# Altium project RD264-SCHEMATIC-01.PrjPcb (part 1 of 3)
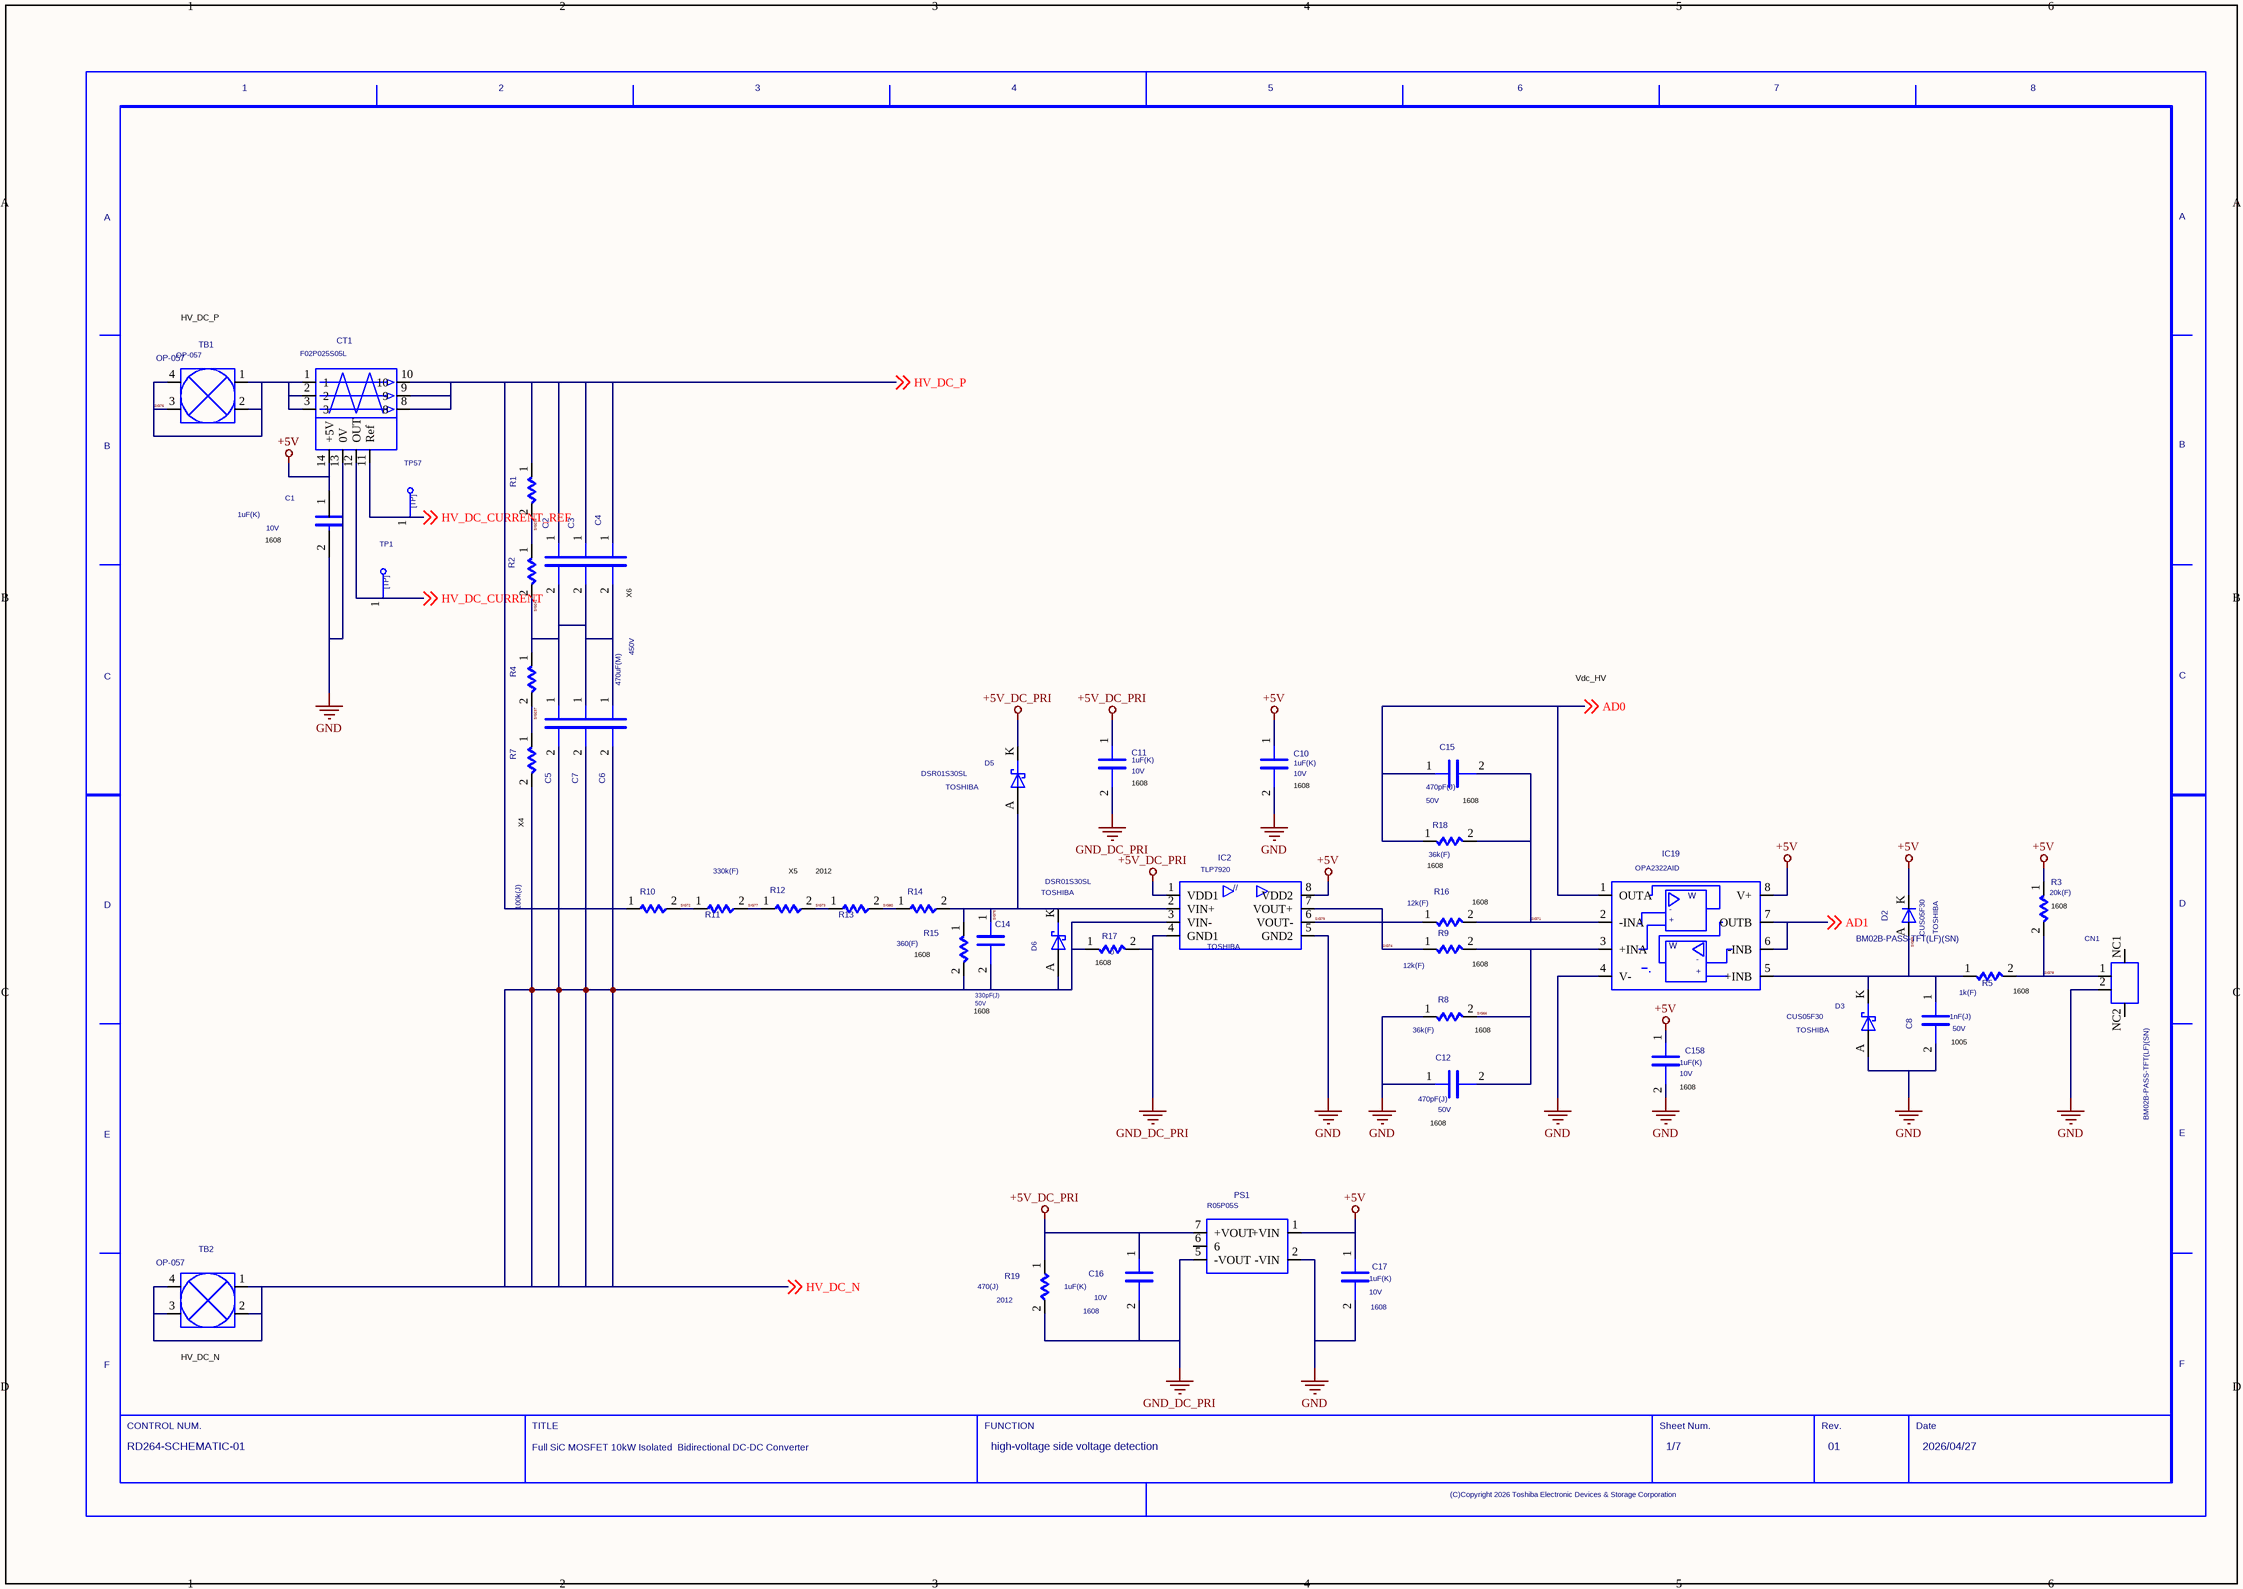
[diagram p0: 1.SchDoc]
7 sheets, 514 parts. Net scope: global (net labels, ports and power ports of the same name join across sheets).
Sheets:
  1.SchDoc
  2.SchDoc
  3.SchDoc
  4.SchDoc
  5.SchDoc
  6.SchDoc
  7.SchDoc

## Sheet 1.SchDoc
size 420 x 297 mm

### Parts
(Parts that share a designator on the sheet are numbered #1, #2 ... from top to bottom, then left to right.)
C1  VAL1: 1uF(K)  VAL2: 10V  (hidden comment: C)
C2  ESMR451VSN471MR40S  (value not drawn)
C3  ESMR451VSN471MR40S  (value not drawn)
C4  VAL1: 470uF(M)  VAL2: 450V  (hidden comment: ESMR451VSN471MR40S)
C5  ESMR451VSN471MR40S  (value not drawn)
C6  ESMR451VSN471MR40S  (value not drawn)
C7  ESMR451VSN471MR40S  (value not drawn)
C8  VAL1: 1nF(J)  VAL2: 50V  (hidden comment: GRM1555C1H102JA01D)
C10  VAL1: 1uF(K)  VAL2: 10V  (hidden comment: GRM188R71A105KA61D)
C11  VAL1: 1uF(K)  VAL2: 10V  (hidden comment: GRM188R71A105KA61D)
C12  VAL1: 470pF(J)  VAL2: 50V  (hidden comment: GRM1885C1H471JA01D)
C14  VAL1: 330pF(J)  VAL2: 50V  (hidden comment: GRM1885C1H331JA01D)
C15  VAL1: 470pF(J)  VAL2: 50V  (hidden comment: GRM1885C1H471JA01D)
C16  VAL1: 1uF(K)  VAL2: 10V  SIZECODESMD: 1608  (hidden comment: GRM188R71A105KA61D)
C17  VAL1: 1uF(K)  VAL2: 10V  SIZECODESMD: 1608  (hidden comment: GRM188R71A105KA61D)
C158  VAL1: 1uF(K)  VAL2: 10V  (hidden comment: GRM188R71A105KA61D)
CN1  BM02B-PASS-TFT(LF)(SN)
CT1  F02P025S05L
D2  USERCOMPTEXT3: TOSHIBA  (hidden comment: CUS05F30)
D3  VAL3: CUS05F30  USERCOMPTEXT3: TOSHIBA  (hidden comment: SBD)
D5  VAL3: DSR01S30SL  USERCOMPTEXT3: TOSHIBA  (hidden comment: SBD)
D6  VAL3: DSR01S30SL  USERCOMPTEXT3: TOSHIBA  (hidden comment: SBD)
IC2  VAL3: TLP7920  USERCOMPTEXT3: TOSHIBA  (hidden comment: TLP7920(LF5,TP5))
IC19  VAL3: OPA2322AID  (hidden comment: OPA2322AIDGKR)
PS1  R05P05S
R1  ROX5SJ100K  (value not drawn)
R2  ROX5SJ100K  (value not drawn)
R3  VAL1: 20k(F)  (hidden comment: RK73H1JTTD2002F)
R4  ROX5SJ100K  (value not drawn)
R5  VAL1: 1k(F)  (hidden comment: RK73H1JTTD1001F)
R7  VAL1: 100k(J)  (hidden comment: ROX5SJ100K)
R8  VAL1: 36k(F)  (hidden comment: RK73G1JTTD3602F)
R9  VAL1: 12k(F)  (hidden comment: RK73G1JTTD1202F)
R10  RK73H2ATTD3303F  (value not drawn)
R11  RK73H2ATTD3303F  (value not drawn)
R12  VAL1: 330k(F)  (hidden comment: RK73H2ATTD3303F)
R13  RK73H2ATTD3303F  (value not drawn)
R14  RK73H2ATTD3303F  (value not drawn)
R15  VAL1: 360(F)  (hidden comment: RK73G1JTTD3600F)
R16  VAL1: 12k(F)  (hidden comment: RK73G1JTTD1202F)
R17  VAL1: 0  (hidden comment: RK73Z1JTTD)
R18  VAL1: 36k(F)  (hidden comment: RK73G1JTTD3602F)
R19  VAL1: 470(J)  SIZECODESMD: 2012  (hidden comment: RK73B2ATTD471J)
TB1  OP-057
TB2  OP-057
TP1  TP  (value not drawn)
TP57  TP  (value not drawn)
U?#1  DATE: 2026/04/27  DRAWINGNUMBER: RD264-SCHEMATIC-01  TITLE: Full SiC MOSFET 10kW Isolated / Bidirectional DC-DC Converter  FUNCTION: high-voltage side voltage detection  SHEETNUMBER: 1/7  REVISION: 01  (hidden comment: WAKU_DEF100)

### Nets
+5V: C1.1 C10.1 C17.1 C158.1 CT1.14(+5V) D2.K(C) IC2.8(VDD2) IC19.8(V+) PS1.1(+VIN) R3.1
+5V_DC_PRI: C11.1 C16.1 D5.K(C) IC2.1(VDD1) PS1.7(+VOUT) R19.1
GND: C1.2 C8.2 C10.2 C12.1 C17.2 C158.2 CN1.2 CT1.13(0V) D3.A IC2.5(GND2) IC19.4(V-) PS1.2(-VIN) R8.1
GND_DC_PRI: C11.2 C16.2 IC2.4(GND1) PS1.5(-VOUT) R17.2 R19.2
AD0: C15.1 IC19.1(OUTA) R18.1 ; off-sheet AD0
AD1: IC19.6(-INB) IC19.7(OUTB) ; off-sheet AD1
HV_DC_CURRENT: CT1.12(OUT) TP1.1 ; off-sheet HV_DC_CURRENT
HV_DC_CURRENT_REF: CT1.11(Ref) TP57.1 ; off-sheet HV_DC_CURRENT_REF
HV_DC_N: C5.2 C6.2 C7.2 C14.2 D6.A IC2.3(VIN-) R7.2 R15.2 R17.1 TB2.1 TB2.2 TB2.3 TB2.4 ; off-sheet HV_DC_N
HV_DC_P: C2.1 C3.1 C4.1 CT1.8 CT1.9 CT1.10 R1.1 R10.1 ; off-sheet HV_DC_P
SIG66: C12.2 IC19.3(+INA) R8.2 R9.2
SIG69: C8.1 D2.A D3.K(C) IC19.5(+INB) R5.1
SIG71: C15.2 IC19.2(-INA) R16.2 R18.2
SIG72: R10.2 R11.1
SIG73: R12.2 R13.1
SIG74: IC2.7(VOUT+) R9.1
SIG75: C14.1 D5.A D6.K(C) IC2.2(VIN+) R14.2 R15.1
SIG76: CT1.1 CT1.2 CT1.3 TB1.1 TB1.2 TB1.3 TB1.4
SIG77: R11.2 R12.1
SIG78: CN1.1 R3.2 R5.2
SIG79: IC2.6(VOUT-) R16.1
SIG80: R13.2 R14.1
SIG237: R4.2 R7.1
SIG238: R1.2 R2.1
SIG241: C2.2 C3.2 C4.2 C5.1 C6.1 C7.1 R2.2 R4.1

Not connected (* = marked no-connect by the designer): CN1 NC1(P1) NC2(P2); PS1 6

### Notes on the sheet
- HV_DC_P
- (near C1) 1608
- (near C4) X6
- Vdc_HV
- (near C11) 1608
- (near C10) 1608
- 1608
- (near R7) X4
- (near R18) 1608
- (near R12) X5
- 2012
- (near R16) 1608
- (near R3) 1608
- (near R17) 1608
- (near R9) 1608
- (near R5) 1608
- (near R8) 1608
- (near C8) 1005
- (near C12) 1608
- (near C158) 1608
- (near TB2) HV_DC_N

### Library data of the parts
C1 = C: OriginalSymbolOrigin: (2540,7620); COMP: C-GRM188R71A105KA61D
C2 = C_Dup1: ORIGINALSYMBOLORIGIN: (0,4826); COMP: C-ESMR451VSN471MR40S; TIME: 14:31:23; UPDATEUSER: t5459927; SAVECOUNT: 1; INSTANCENAME: INS17096676; REFERENCE TEMPLATE: C; COMPONENTNAME: C_C.Normal_package; NOTE: 470uF 450V; VAL1: 470uF(M); VAL2: 450V
C3 = C_Dup1: ORIGINALSYMBOLORIGIN: (0,4826); COMP: C-ESMR451VSN471MR40S; TIME: 14:31:23; UPDATEUSER: t5459927; SAVECOUNT: 1; INSTANCENAME: INS17096668; REFERENCE TEMPLATE: C; COMPONENTNAME: C_C.Normal_package; NOTE: 470uF 450V; VAL1: 470uF(M); VAL2: 450V
C4 = C_Dup1: ORIGINALSYMBOLORIGIN: (0,4826); COMP: C-ESMR451VSN471MR40S; TIME: 14:31:23; UPDATEUSER: t5459927; SAVECOUNT: 1; INSTANCENAME: INS17096660; REFERENCE TEMPLATE: C; COMPONENTNAME: C_C.Normal_package; NOTE: 470uF 450V
C5 = C_Dup1: ORIGINALSYMBOLORIGIN: (0,4826); COMP: C-ESMR451VSN471MR40S; TIME: 14:31:23; UPDATEUSER: t5459927; SAVECOUNT: 1; INSTANCENAME: INS17096734; REFERENCE TEMPLATE: C; COMPONENTNAME: C_C.Normal_package; NOTE: 470uF 450V; VAL1: 470uF(M); VAL2: 450V
C6 = C_Dup1: ORIGINALSYMBOLORIGIN: (0,4826); COMP: C-ESMR451VSN471MR40S; TIME: 14:31:23; UPDATEUSER: t5459927; SAVECOUNT: 1; INSTANCENAME: INS17096718; REFERENCE TEMPLATE: C; COMPONENTNAME: C_C.Normal_package; NOTE: 470uF 450V; VAL1: 470uF(M); VAL2: 450V
C7 = C_Dup1: ORIGINALSYMBOLORIGIN: (0,4826); COMP: C-ESMR451VSN471MR40S; TIME: 14:31:23; UPDATEUSER: t5459927; SAVECOUNT: 1; INSTANCENAME: INS17096726; REFERENCE TEMPLATE: C; COMPONENTNAME: C_C.Normal_package; NOTE: 470uF 450V; VAL1: 470uF(M); VAL2: 450V
C8 = C_Dup1: ORIGINALSYMBOLORIGIN: (0,4826); COMP: C-GRM1555C1H102JA01D; TIME: 14:31:23; UPDATEUSER: t5459927; SAVECOUNT: 1; INSTANCENAME: INS17857547; REFERENCE TEMPLATE: C; COMPONENTNAME: C_C.Normal_package; NOTE: 1000pF 50V
C10 = C_Dup1: ORIGINALSYMBOLORIGIN: (0,4826); COMP: C-GRM188R71A105KA61D; TIME: 14:31:23; UPDATEUSER: t5459927; SAVECOUNT: 1; INSTANCENAME: INS17096768; REFERENCE TEMPLATE: C; COMPONENTNAME: C_C.Normal_package; NOTE: 1uF 10V; OLDCOMPONENTID: 240
C11 = C_Dup1: ORIGINALSYMBOLORIGIN: (0,4826); COMP: C-GRM188R71A105KA61D; TIME: 14:31:23; UPDATEUSER: t5459927; SAVECOUNT: 1; INSTANCENAME: INS17096804; REFERENCE TEMPLATE: C; COMPONENTNAME: C_C.Normal_package; NOTE: 1uF 10V
C12 = C_Dup1: ORIGINALSYMBOLORIGIN: (0,4826); COMP: C-GRM1885C1H471JA01D; TIME: 14:31:23; UPDATEUSER: t5459927; SAVECOUNT: 1; INSTANCENAME: INS17096780; REFERENCE TEMPLATE: C; COMPONENTNAME: C_C.Normal_package; NOTE: 470pF 50V
C14 = C_Dup1: ORIGINALSYMBOLORIGIN: (0,4826); COMP: C-GRM1885C1H331JA01D; TIME: 14:31:23; UPDATEUSER: t5459927; SAVECOUNT: 1; INSTANCENAME: INS17096988; REFERENCE TEMPLATE: C; COMPONENTNAME: C_C.Normal_package; NOTE: 330pF 50V
C15 = C_Dup1: ORIGINALSYMBOLORIGIN: (0,4826); COMP: C-GRM1885C1H471JA01D; TIME: 14:31:23; UPDATEUSER: t5459927; SAVECOUNT: 1; INSTANCENAME: INS17097028; REFERENCE TEMPLATE: C; COMPONENTNAME: C_C.Normal_package; NOTE: 470pF 50V
C16 = C_Dup1: ORIGINALSYMBOLORIGIN: (0,4826); COMP: C-GRM188R71A105KA61D; TIME: 14:31:23; UPDATEUSER: t5459927; SAVECOUNT: 1; INSTANCENAME: INS17856707; REFERENCE TEMPLATE: C; COMPONENTNAME: C_C.Normal_package; NOTE: 1uF 10V
C17 = C_Dup1: ORIGINALSYMBOLORIGIN: (0,4826); COMP: C-GRM188R71A105KA61D; TIME: 14:31:23; UPDATEUSER: t5459927; SAVECOUNT: 1; INSTANCENAME: INS17857178; REFERENCE TEMPLATE: C; COMPONENTNAME: C_C.Normal_package; NOTE: 1uF 10V
C158 = C_Dup1: ORIGINALSYMBOLORIGIN: (0,4826); COMP: C-GRM188R71A105KA61D; TIME: 14:31:23; UPDATEUSER: t5459927; SAVECOUNT: 1; INSTANCENAME: INS17335587; REFERENCE TEMPLATE: C; COMPONENTNAME: C_C.Normal_package; NOTE: 1uF 10V
CN1 = BM02B_PASS_TFT_LF__SN_: PA Connector; COMP: CN-BM02B-PASS-TFT_LF_SN; MAKER: JST; NOTE: 2pin; TIME: 14:31:25; UPDATEUSER: t5459927; SAVECOUNT: 1; SAVEAREA0: -5711,-13828,12927,-163; OriginalSymbolOrigin: (0,0); INSTANCENAME: INS17146588; REFERENCE TEMPLATE: CN; COMPONENTNAME: BM02B-PASS-TFT(LF)(SN)_BM02B-PASS-TFT(LF)(SN).Normal_package
CT1 = F02P025S05L: Currnt Transducer; COMP: CT-F02P025S05L; MAKER: Tamura; NOTE: 25At; TIME: 14:31:25; UPDATEUSER: t5459927; UPDATETIME: 08:52:16; SAVECOUNT: 3; SAVEAREA0: -26887,-18217,41699,10476; OriginalSymbolOrigin: (0,0)
D2 = D: UPDATEUSER: t5459927; COMP: D-CUS05F30; UPDATETIME: 14:31:23; SAVECOUNT: 1; SAVEAREA0: -225,-91,12804,7836; ORIGINALSYMBOLORIGIN: (0,0); INSTANCENAME: INS17146580; COMPONENTNAME: D_D.Normal_package
D3 D5 D6 = SBD: SAVEAREA0: -4630,-153,17114,13055; TIME: 14:49:55; UPDATEUSER: fukuda-y; UPDATETIME: 08:16:22; SAVECOUNT: 9; OriginalSymbolOrigin: (5080,5080)
IC2 = TLP7920_LF5: Isolation Amplifier; COMP: IC-TLP7920_LF5_TP5; TIME: 14:31:23; UPDATEUSER: t5459927; UPDATETIME: 14:29:27; SAVECOUNT: 3; SAVEAREA0: -27477,-19134,50054,13301; OriginalSymbolOrigin: (0,0)
IC19 = OPA2322AIDGKR: IC OPAMP; COMP: IC-OPA2322AID; MAKER: Texas Instruments; NOTE: Dual; TIME: 14:31:24; UPDATEUSER: t5459927; UPDATETIME: 14:36:00; SAVECOUNT: 3; SAVEAREA0: -54405,-42613,83055,14894; OriginalSymbolOrigin: (0,0)
PS1 = R05P05S: DCDC Converter; COMP: PS-R05P05S; MAKER: RECOM; NOTE: 5V in 5V out; TIME: 14:31:25; UPDATEUSER: t5459927; UPDATETIME: 15:35:32; SAVECOUNT: 4; SAVEAREA0: -11227,-12811,26358,2912; OriginalSymbolOrigin: (0,0)
R1 = R: ORIGINALSYMBOLORIGIN: (0,0); COMP: R-ROX5SJ100K; TIME: 14:31:23; UPDATEUSER: t5459927; SAVECOUNT: 1; INSTANCENAME: INS17096650; COMPONENTNAME: R_R.Normal_package; NOTE: 100kohm 5W; VAL1: 100k(J); VAL2: 5w
R2 = R: ORIGINALSYMBOLORIGIN: (0,0); COMP: R-ROX5SJ100K; TIME: 14:31:23; UPDATEUSER: t5459927; SAVECOUNT: 1; INSTANCENAME: INS17096684; COMPONENTNAME: R_R.Normal_package; NOTE: 100kohm 5W; VAL1: 100k(J); VAL2: 5w
R3 = R: ORIGINALSYMBOLORIGIN: (0,0); COMP: R-RK73H1JTTD2002F; TIME: 14:31:23; UPDATEUSER: t5459927; SAVECOUNT: 1; INSTANCENAME: INS17146572; COMPONENTNAME: R_R.Normal_package; NOTE: 20kohm 0.1W; VAL2: 100mw
R4 = R: ORIGINALSYMBOLORIGIN: (0,0); COMP: R-ROX5SJ100K; TIME: 14:31:23; UPDATEUSER: t5459927; SAVECOUNT: 1; INSTANCENAME: INS17096742; COMPONENTNAME: R_R.Normal_package; NOTE: 100kohm 5W; VAL1: 100k(J); VAL2: 5w
R5 = R: ORIGINALSYMBOLORIGIN: (0,0); COMP: R-RK73H1JTTD1001F; TIME: 14:31:23; UPDATEUSER: t5459927; SAVECOUNT: 1; INSTANCENAME: INS17858314; COMPONENTNAME: R_R.Normal_package; NOTE: 1.0kohm 0.1W; VAL2: 125mw
R7 = R: ORIGINALSYMBOLORIGIN: (0,0); COMP: R-ROX5SJ100K; TIME: 14:31:23; UPDATEUSER: t5459927; SAVECOUNT: 1; INSTANCENAME: INS17096788; COMPONENTNAME: R_R.Normal_package; NOTE: 100kohm 5W; VAL2: 5w
R8 = R: ORIGINALSYMBOLORIGIN: (0,0); COMP: R-RK73G1JTTD3602F; TIME: 14:31:23; UPDATEUSER: t5459927; SAVECOUNT: 1; INSTANCENAME: INS17096812; COMPONENTNAME: R_R.Normal_package; NOTE: 36kohm 0.1W; VAL2: 100mw
R9 = R: ORIGINALSYMBOLORIGIN: (0,0); COMP: R-RK73G1JTTD1202F; TIME: 14:31:23; UPDATEUSER: t5459927; SAVECOUNT: 1; INSTANCENAME: INS17096836; COMPONENTNAME: R_R.Normal_package; NOTE: 12kohm 0.1W; VAL2: 100mw
R10 = R: PART NUMBER: TMP-977; ORIGINALSYMBOLORIGIN: (0,0); COMP: R-RK73H2ATTD3303F; TIME: 14:31:23; UPDATEUSER: t5459927; SAVECOUNT: 1; INSTANCENAME: INS17779029; COMPONENTNAME: R_R.Normal_package; NOTE: 330kohm 0.25W; VAL1: 330k(F); VAL2: 250mw
R11 = R: PART NUMBER: TMP-977; ORIGINALSYMBOLORIGIN: (0,0); COMP: R-RK73H2ATTD3303F; TIME: 14:31:23; UPDATEUSER: t5459927; SAVECOUNT: 1; INSTANCENAME: INS17779073; COMPONENTNAME: R_R.Normal_package; NOTE: 330kohm 0.25W; VAL1: 330k(F); VAL2: 250mw
R12 = R: PART NUMBER: TMP-977; ORIGINALSYMBOLORIGIN: (0,0); COMP: R-RK73H2ATTD3303F; TIME: 14:31:23; UPDATEUSER: t5459927; SAVECOUNT: 1; INSTANCENAME: INS17779223; COMPONENTNAME: R_R.Normal_package; NOTE: 330kohm 0.25W; VAL2: 250mw
R13 = R: PART NUMBER: TMP-977; ORIGINALSYMBOLORIGIN: (0,0); COMP: R-RK73H2ATTD3303F; TIME: 14:31:23; UPDATEUSER: t5459927; SAVECOUNT: 1; INSTANCENAME: INS17779250; COMPONENTNAME: R_R.Normal_package; NOTE: 330kohm 0.25W; VAL1: 330k(F); VAL2: 250mw
R14 = R: PART NUMBER: TMP-977; ORIGINALSYMBOLORIGIN: (0,0); COMP: R-RK73H2ATTD3303F; TIME: 14:31:23; UPDATEUSER: t5459927; SAVECOUNT: 1; INSTANCENAME: INS17779350; COMPONENTNAME: R_R.Normal_package; NOTE: 330kohm 0.25W; VAL1: 330k(F); VAL2: 250mw
R15 = R: ORIGINALSYMBOLORIGIN: (0,0); COMP: R-RK73G1JTTD3600F; TIME: 14:31:23; UPDATEUSER: t5459927; SAVECOUNT: 1; INSTANCENAME: INS17096996; COMPONENTNAME: R_R.Normal_package; NOTE: 360ohm 0.1W; VAL2: 100mw
R16 = R: ORIGINALSYMBOLORIGIN: (0,0); COMP: R-RK73G1JTTD1202F; TIME: 14:31:23; UPDATEUSER: t5459927; SAVECOUNT: 1; INSTANCENAME: INS17096888; COMPONENTNAME: R_R.Normal_package; NOTE: 12kohm 0.1W; VAL2: 100mw
R17 = R: ORIGINALSYMBOLORIGIN: (0,0); COMP: R-RK73Z1JTTD; TIME: 14:31:23; UPDATEUSER: t5459927; SAVECOUNT: 1; INSTANCENAME: INS17097020; COMPONENTNAME: R_R.Normal_package; NOTE: 0ohm 0.1W
R18 = R: ORIGINALSYMBOLORIGIN: (0,0); COMP: R-RK73G1JTTD3602F; TIME: 14:31:23; UPDATEUSER: t5459927; SAVECOUNT: 1; INSTANCENAME: INS17096966; COMPONENTNAME: R_R.Normal_package; NOTE: 36kohm 0.1W; VAL2: 100mw
R19 = R: ORIGINALSYMBOLORIGIN: (0,0); COMP: R-RK73B2ATTD471J; TIME: 14:31:23; UPDATEUSER: t5459927; SAVECOUNT: 1; INSTANCENAME: INS17417018; COMPONENTNAME: R_R.Normal_package; NOTE: 470ohm 0.25W; VAL2: 250mw
TB1 = OP_057: Terminal Block; PART NUMBER: TMP-784; COMP: TB-OP-057; MAKER: Osada; NOTE: 85A M5; TIME: 14:31:25; UPDATEUSER: t5459927; SAVECOUNT: 1; SAVEAREA0: -3160,-10780,12927,1014; OriginalSymbolOrigin: (0,0); INSTANCENAME: INS17363560; REFERENCE TEMPLATE: TB; COMPONENTNAME: OP-057_OP-057.Normal_package
TB2 = OP_057: Terminal Block; PART NUMBER: TMP-784; COMP: TB-OP-057; MAKER: Osada; NOTE: 85A M5; TIME: 14:31:25; UPDATEUSER: t5459927; SAVECOUNT: 1; SAVEAREA0: -3160,-10780,12927,1014; OriginalSymbolOrigin: (0,0); INSTANCENAME: INS17363646; REFERENCE TEMPLATE: TB; COMPONENTNAME: OP-057_OP-057.Normal_package
TP1 TP57 = TP: TIME: 16:12:21; UPDATEUSER: fukuda-y; UPDATETIME: 16:18:11; SAVECOUNT: 2; SAVEAREA0: -242,-92,12810,7836; OriginalSymbolOrigin: (0,7620); VAL3: HK-3-G; COMP: TP-HK-3-G
U?#1 = WAKU_DEF100: PLOTTIME: HH:MM; SAVEAREA0: 204655,-40163,430411,63902; TIME: 14:30:25; UPDATEUSER: t5459927; UPDATETIME: 14:22:34; SAVECOUNT: 7; OriginalSymbolOrigin: (10160,284480); SHTSAVECOUNT: 16

## Sheet 2.SchDoc
size 420 x 297 mm
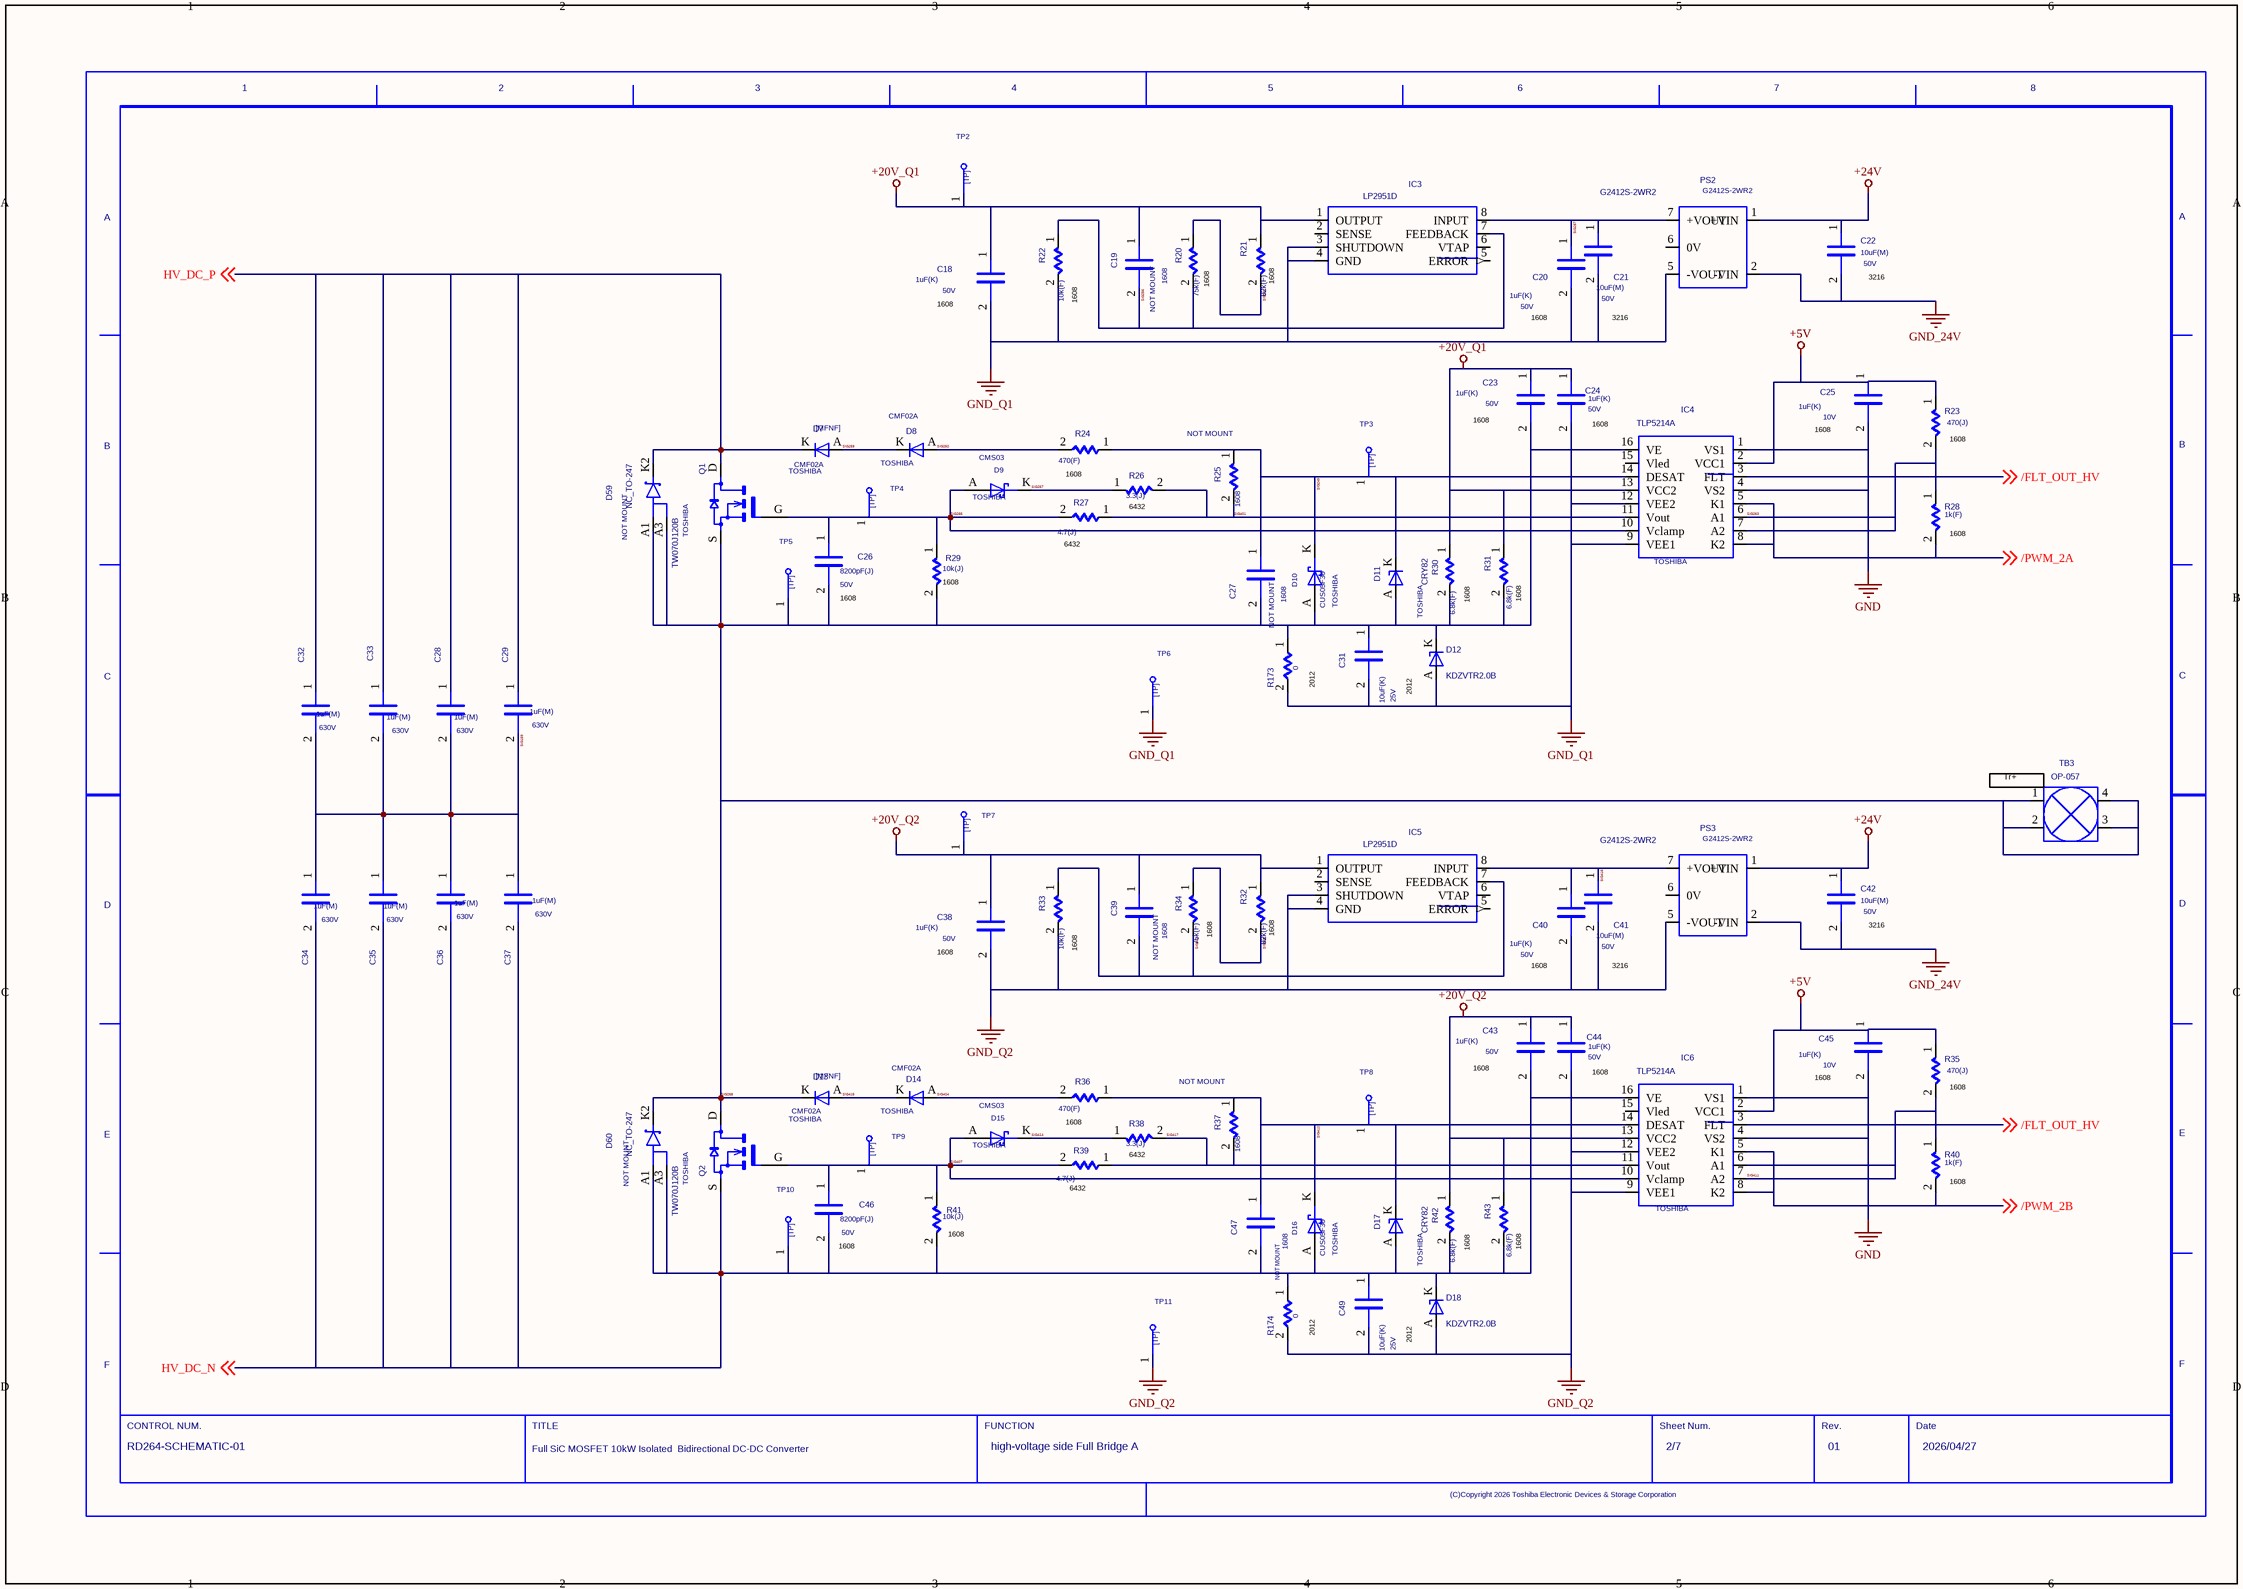
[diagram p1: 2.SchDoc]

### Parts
(Parts that share a designator on the sheet are numbered #1, #2 ... from top to bottom, then left to right.)
C18  VAL2: 50V  VAL1: 1uF(K)  (hidden comment: GRM188R61H105KAALD)
C19  SIZECODESMD: 1608  NOTMOUNT: NOT MOUNT  (hidden comment: NC_C1608)
C20  VAL2: 50V  VAL1: 1uF(K)  (hidden comment: GRM188R61H105KAALD)
C21  VAL2: 50V  VAL1: 10uF(M)  (hidden comment: GRM31CR61H106MA12L)
C22  VAL2: 50V  VAL1: 10uF(M)  (hidden comment: GRM31CR61H106MA12L)
C23  VAL2: 50V  VAL1: 1uF(K)  (hidden comment: GRM188R61H105KAALD)
C24  VAL1: 1uF(K)  VAL2: 50V  (hidden comment: GRM188R61H105KAALD)
C25  VAL1: 1uF(K)  VAL2: 10V  (hidden comment: GRM188R71A105KA61D)
C26  VAL1: 8200pF(J)  VAL2: 50V  (hidden comment: GRM1885C1H332JA01D)
C27  SIZECODESMD: 1608  NOTMOUNT: NOT MOUNT  (hidden comment: NC_C1608)
C28  VAL1: 1uF(M)  VAL2: 630V  (hidden comment: CKG57NX7T2J105M500JH)
C29  VAL1: 1uF(M)  VAL2: 630V  (hidden comment: CKG57NX7T2J105M500JH)
C31  VAL2: 25V  VAL1: 10uF(K)  (hidden comment: GRM21BC71E106KE11L)
C32  VAL1: 1uF(M)  VAL2: 630V  (hidden comment: CKG57NX7T2J105M500JH)
C33  VAL1: 1uF(M)  VAL2: 630V  (hidden comment: CKG57NX7T2J105M500JH)
C34  VAL1: 1uF(M)  VAL2: 630V  (hidden comment: CKG57NX7T2J105M500JH)
C35  VAL1: 1uF(M)  VAL2: 630V  (hidden comment: CKG57NX7T2J105M500JH)
C36  VAL1: 1uF(M)  VAL2: 630V  (hidden comment: CKG57NX7T2J105M500JH)
C37  VAL1: 1uF(M)  VAL2: 630V  (hidden comment: CKG57NX7T2J105M500JH)
C38  VAL1: 1uF(K)  VAL2: 50V  (hidden comment: GRM188R61H105KAALD)
C39  NOTMOUNT: NOT MOUNT  SIZECODESMD: 1608  (hidden comment: NC_C1608)
C40  VAL1: 1uF(K)  VAL2: 50V  (hidden comment: GRM188R61H105KAALD)
C41  VAL1: 10uF(M)  VAL2: 50V  (hidden comment: GRM31CR61H106MA12L)
C42  VAL1: 10uF(M)  VAL2: 50V  (hidden comment: GRM31CR61H106MA12L)
C43  VAL1: 1uF(K)  VAL2: 50V  (hidden comment: GRM188R61H105KAALD)
C44  VAL1: 1uF(K)  VAL2: 50V  (hidden comment: GRM188R61H105KAALD)
C45  VAL1: 1uF(K)  VAL2: 10V  (hidden comment: GRM188R71A105KA61D)
C46  VAL1: 8200pF(J)  VAL2: 50V  (hidden comment: GRM1885C1H332JA01D)
C47  NOTMOUNT: NOT MOUNT  SIZECODESMD: 1608  (hidden comment: NC_C1608)
C49  VAL1: 10uF(K)  VAL2: 25V  (hidden comment: GRM21BC71E106KE11L)
D7  USERCOMPTEXT3: TOSHIBA  VAL3: CMF02A  (hidden comment: CMF05)
D8  USERCOMPTEXT3: TOSHIBA  VAL3: CMF02A  (hidden comment: CMF05)
D9  VAL3: CMS03  USERCOMPTEXT3: TOSHIBA  (hidden comment: SBD)
D10  VAL3: CUS05F30  USERCOMPTEXT3: TOSHIBA  (hidden comment: SBD)
D11  CRY82  USERCOMPTEXT3: TOSHIBA
D12  KDZVTR2.0B
D13  VAL3: CMF02A  USERCOMPTEXT3: TOSHIBA  (hidden comment: CMF05)
D14  VAL3: CMF02A  USERCOMPTEXT3: TOSHIBA  (hidden comment: CMF05)
D15  VAL3: CMS03  USERCOMPTEXT3: TOSHIBA  (hidden comment: SBD)
D16  VAL3: CUS05F30  USERCOMPTEXT3: TOSHIBA  (hidden comment: SBD)
D17  CRY82  USERCOMPTEXT3: TOSHIBA
D18  KDZVTR2.0B
D59  NC_TO-247  NOTMOUNT: NOT MOUNT
D60  NC_TO-247  NOTMOUNT: NOT MOUNT
IC3  LP2951D
IC4  TLP5214A  USERCOMPTEXT3: TOSHIBA
IC5  LP2951D
IC6  TLP5214A  USERCOMPTEXT3: TOSHIBA
PS2  G2412S-2WR2
PS3  G2412S-2WR2
Q1  TW070J120B  USERCOMPTEXT3: TOSHIBA
Q2  TW070J120B  USERCOMPTEXT3: TOSHIBA
R20  VAL1: 75k(F)  (hidden comment: RK73H1JTTD7502F)
R21  VAL1: 82k(F)  (hidden comment: RK73H1JTTD8202F)
R22  VAL1: 10k(F)  (hidden comment: RK73H1JTTD1002F)
R23  VAL1: 470(J)  (hidden comment: RK73B1JTTD471J)
R24  VAL1: 470(F)  (hidden comment: ERJ3EKF4700V)
R25  SIZECODESMD: 1608  NOTMOUNT: NOT MOUNT  (hidden comment: NC_R1608)
R26  VAL1: 3.3(J)  (hidden comment: ERJ1TYJ3R3U)
R27  VAL1: 4.7(J)  (hidden comment: ERJ1TYJ4R7U)
R28  VAL1: 1k(F)  (hidden comment: RK73H1JTTD1001F)
R29  VAL1: 10k(J)  (hidden comment: RK73B1JTTD103J)
R30  VAL1: 6.8k(F)  (hidden comment: RK73H1JTTD6801F)
R31  VAL1: 6.8k(F)  (hidden comment: RK73H1JTTD6801F)
R32  VAL1: 82k(F)  (hidden comment: RK73H1JTTD8202F)
R33  VAL1: 10k(F)  (hidden comment: RK73H1JTTD1002F)
R34  VAL1: 75k(F)  (hidden comment: RK73H1JTTD7502F)
R35  VAL1: 470(J)  (hidden comment: RK73B1JTTD471J)
R36  VAL1: 470(F)  (hidden comment: ERJ3EKF4700V)
R37  NOTMOUNT: NOT MOUNT  SIZECODESMD: 1608  (hidden comment: NC_R1608)
R38  VAL1: 3.3(J)  (hidden comment: ERJ1TYJ3R3U)
R39  VAL1: 4.7(J)  (hidden comment: ERJ1TYJ4R7U)
R40  VAL1: 1k(F)  (hidden comment: RK73H1JTTD1001F)
R41  VAL1: 10k(J)  (hidden comment: RK73B1JTTD103J)
R42  VAL1: 6.8k(F)  (hidden comment: RK73H1JTTD6801F)
R43  VAL1: 6.8k(F)  (hidden comment: RK73H1JTTD6801F)
R173  VAL1: 0  (hidden comment: RK73Z2ATTD)
R174  VAL1: 0  (hidden comment: RK73Z2ATTD)
TB3  OP-057
TP2  TP  (value not drawn)
TP3  TP  (value not drawn)
TP4  TP  (value not drawn)
TP5  TP  (value not drawn)
TP6  TP  (value not drawn)
TP7  TP  (value not drawn)
TP8  TP  (value not drawn)
TP9  TP  (value not drawn)
TP10  TP  (value not drawn)
TP11  TP  (value not drawn)
U?#2  DATE: 2026/04/27  DRAWINGNUMBER: RD264-SCHEMATIC-01  TITLE: Full SiC MOSFET 10kW Isolated / Bidirectional DC-DC Converter  FUNCTION: high-voltage side Full Bridge A  SHEETNUMBER: 2/7  REVISION: 01  (hidden comment: WAKU_DEF100)

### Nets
+5V: C25.1 C45.1 IC4.2(VCC1) IC6.2(VCC1) R23.1 R35.1
+20V_Q1: C18.1 C19.1 C23.1 C24.1 IC3.1(OUTPUT) IC4.13(VCC2) R21.1 R30.1 R31.1 TP2.1
+20V_Q2: C38.1 C39.1 C43.1 C44.1 IC5.1(OUTPUT) IC6.13(VCC2) R32.1 R42.1 R43.1 TP7.1
+24V: C22.1 C42.1 PS2.1(+VIN) PS3.1(+VIN)
GND: C25.2 C45.2 IC4.1(VS1) IC4.4(VS2) IC6.1(VS1) IC6.4(VS2)
GND_24V: C22.2 C42.2 PS2.2(-VIN) PS3.2(-VIN)
GND_Q1: C18.2 C20.2 C21.2 C24.2 C31.2 D12.A IC3.3(SHUTDOWN) IC3.4(GND) IC4.9(VEE1) IC4.12(VEE2) PS2.5(-VOUT) R22.2 R173.2 TP6.1
GND_Q2: C38.2 C40.2 C41.2 C44.2 C49.2 D18.A IC5.3(SHUTDOWN) IC5.4(GND) IC6.9(VEE1) IC6.12(VEE2) PS3.5(-VOUT) R33.2 R174.2 TP11.1
/FLT_OUT_HV: IC4.3(FLT) IC6.3(FLT) ; off-sheet /FLT_OUT_HV
/PWM_2A: IC4.5(K1) IC4.8(K2) R28.2 ; off-sheet /PWM_2A
/PWM_2B: IC6.5(K1) IC6.8(K2) R40.2 ; off-sheet /PWM_2B
HV_DC_N: C34.2 C35.2 C36.2 C37.2 C43.2 C46.2 C47.2 C49.1 D16.A D17.A D18.K(C) D60.A1 D60.A3 IC6.16(VE) Q2.S R41.2 R42.2 R43.2 R174.1 TP10.1 ; off-sheet HV_DC_N
HV_DC_P: C28.1 C29.1 C32.1 C33.1 D7.K(C) D59.K2 Q1.D ; off-sheet HV_DC_P
SIG159: C28.2 C29.2 C32.2 C33.2 C34.1 C35.1 C36.1 C37.1
SIG249: C27.1 D10.K(C) D11.K(C) IC4.14(DESAT) R24.1 R25.1 TP3.1
SIG250: D8.A R24.2
SIG253: R20.1 R21.2
SIG256: C19.2 IC3.7(FEEDBACK) R20.2 R22.1
SIG257: D9.K(C) R26.1
SIG258: D7.A D8.K(C)
SIG263: IC4.6(A1) IC4.7(A2) R23.2 R28.1
SIG265: C26.1 D9.A IC4.10(Vclamp) Q1.G R27.2 R29.1 TP4.1
SIG267: C20.1 C21.1 IC3.8(INPUT) PS2.7(+VOUT)
SIG268: C23.2 C26.2 C27.2 C31.1 D10.A D11.A D12.K(C) D13.K(C) D59.A1 D59.A3 D60.K2 IC4.16(VE) Q1.S Q2.D R29.2 R30.2 R31.2 R173.1 TB3.1 TB3.2 TB3.3 TB3.4 TP5.1
SIG401: IC4.11(Vout) R25.2 R26.2 R27.1
SIG402: C39.2 IC5.7(FEEDBACK) R33.1 R34.2
SIG404: D14.A R36.2
SIG405: R32.2 R34.1
SIG407: C46.1 D15.A IC6.10(Vclamp) Q2.G R39.2 R41.1 TP9.1
SIG411: IC6.6(A1) IC6.7(A2) R35.2 R40.1
SIG413: C47.1 D16.K(C) D17.K(C) IC6.14(DESAT) R36.1 R37.1 TP8.1
SIG414: D15.K(C) R38.1
SIG415: D13.A D14.K(C)
SIG416: C40.1 C41.1 IC5.8(INPUT) PS3.7(+VOUT)
SIG417: IC6.11(Vout) R37.2 R38.2 R39.1

Not connected (* = marked no-connect by the designer): IC3 2(SENSE) 5(ERROR) 6(VTAP); IC4 15(Vled); IC5 2(SENSE) 5(ERROR) 6(VTAP); IC6 15(Vled); PS2 6(0V); PS3 6(0V)

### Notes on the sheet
- (near C18) 1608
- (near R22) 1608
- (near R20) 1608
- (near R21) 1608
- 1608
- 3216
- (near C22) 3216
- (near C23) 1608
- (near C24) 1608
- (near C25) 1608
- (near R23) 1608
- (near R24) 1608
- (near R26) 6432
- (near C26) 1608
- (near R29) 1608
- (near R27) 6432
- (near R30) 1608
- (near R31) 1608
- (near R28) 1608
- (near R173) 2012
- 2012
- (near TB3) Tr+
- (near R34) 1608
- (near R32) 1608
- (near C42) 3216
- (near C38) 1608
- (near R33) 1608
- (near C43) 1608
- (near C44) 1608
- (near R36) 1608
- (near C45) 1608
- (near R35) 1608
- (near R39) 6432
- (near R38) 6432
- (near R40) 1608
- (near C46) 1608
- (near R41) 1608
- (near R42) 1608
- (near R43) 1608
- (near R174) 2012

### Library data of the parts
C18 = C_Dup1: ORIGINALSYMBOLORIGIN: (0,4826); COMP: C-GRM188R61H105KAALD; TIME: 14:31:23; UPDATEUSER: t5459927; SAVECOUNT: 1; NOTE: 1uF 50V; FUNCN: C_C.Normal_package; REFERENCE TEMPLATE: C; INSTANCENAME: INS16721371
C19 = C_Dup1: ORIGINALSYMBOLORIGIN: (0,4826); COMP: C-1608_NM; TIME: 14:31:23; UPDATEUSER: t5459927; SAVECOUNT: 1; FUNCN: C_C.Normal_package; REFERENCE TEMPLATE: C; INSTANCENAME: INS16721315
C20 = C_Dup1: ORIGINALSYMBOLORIGIN: (0,4826); COMP: C-GRM188R61H105KAALD; TIME: 14:31:23; UPDATEUSER: t5459927; SAVECOUNT: 1; NOTE: 1uF 50V; FUNCN: C_C.Normal_package; REFERENCE TEMPLATE: C; INSTANCENAME: INS15595921
C21 = C_Dup1: ORIGINALSYMBOLORIGIN: (0,4826); COMP: C-GRM31CR61H106MA12L; TIME: 14:31:23; UPDATEUSER: t5459927; SAVECOUNT: 1; NOTE: 10uF 50V; FUNCN: C_C.Normal_package; REFERENCE TEMPLATE: C; INSTANCENAME: INS15595987
C22 = C_Dup1: ORIGINALSYMBOLORIGIN: (0,4826); COMP: C-GRM31CR61H106MA12L; TIME: 14:31:23; UPDATEUSER: t5459927; SAVECOUNT: 1; NOTE: 10uF 50V; FUNCN: C_C.Normal_package; REFERENCE TEMPLATE: C; INSTANCENAME: INS15596097
C23 = C_Dup1: ORIGINALSYMBOLORIGIN: (0,4826); COMP: C-GRM188R61H105KAALD; TIME: 14:31:23; UPDATEUSER: t5459927; SAVECOUNT: 1; NOTE: 1uF 50V; FUNCN: C_C.Normal_package; REFERENCE TEMPLATE: C; INSTANCENAME: INS15596075
C24 C44 = C_Dup1: ORIGINALSYMBOLORIGIN: (0,4826); COMP: C-GRM188R61H105KAALD; TIME: 14:31:23; UPDATEUSER: t5459927; SAVECOUNT: 1; INSTANCENAME: INS15596185; REFERENCE TEMPLATE: C; COMPONENTNAME: C_C.Normal_package; NOTE: 1uF 50V
C25 C45 = C_Dup1: ORIGINALSYMBOLORIGIN: (0,4826); COMP: C-GRM188R71A105KA61D; TIME: 14:31:23; UPDATEUSER: t5459927; SAVECOUNT: 1; INSTANCENAME: INS15595789; REFERENCE TEMPLATE: C; COMPONENTNAME: C_C.Normal_package; NOTE: 1uF 10V
C26 C46 = C_Dup1: ORIGINALSYMBOLORIGIN: (0,4826); COMP: C-GRM1885C1H332JA01D; TIME: 14:31:23; UPDATEUSER: t5459927; SAVECOUNT: 1; INSTANCENAME: INS15595745; REFERENCE TEMPLATE: C; COMPONENTNAME: C_C.Normal_package; NOTE: 3300pF 50V
C27 = C_Dup1: ORIGINALSYMBOLORIGIN: (0,4826); COMP: C-1608_NM; TIME: 14:31:23; UPDATEUSER: t5459927; SAVECOUNT: 1; FUNCN: C_C.Normal_package; REFERENCE TEMPLATE: C; INSTANCENAME: INS15596281
C28 = C_Dup1: ORIGINALSYMBOLORIGIN: (0,4826); COMP: C-CKG57NX7T2J105M500JH; TIME: 14:31:23; UPDATEUSER: t5459927; SAVECOUNT: 1; INSTANCENAME: INS15645445; REFERENCE TEMPLATE: C; COMPONENTNAME: C_C.Normal_package; NOTE: 1uF 650V
C29 = C_Dup1: ORIGINALSYMBOLORIGIN: (0,4826); COMP: C-CKG57NX7T2J105M500JH; TIME: 14:31:23; UPDATEUSER: t5459927; SAVECOUNT: 1; INSTANCENAME: INS15645292; REFERENCE TEMPLATE: C; COMPONENTNAME: C_C.Normal_package; NOTE: 1uF 650V
C31 = C_Dup1: ORIGINALSYMBOLORIGIN: (0,4826); COMP: C-GRM21BC71E106KE11L; TIME: 14:31:23; UPDATEUSER: t5459927; SAVECOUNT: 1; NOTE: 10uF 25V; FUNCN: C_C.Normal_package; REFERENCE TEMPLATE: C; INSTANCENAME: INS17875665
C32 = C_Dup1: ORIGINALSYMBOLORIGIN: (0,4826); COMP: C-CKG57NX7T2J105M500JH; TIME: 14:31:23; UPDATEUSER: t5459927; SAVECOUNT: 1; INSTANCENAME: INS15645741; REFERENCE TEMPLATE: C; COMPONENTNAME: C_C.Normal_package; NOTE: 1uF 650V
C33 = C_Dup1: ORIGINALSYMBOLORIGIN: (0,4826); COMP: C-CKG57NX7T2J105M500JH; TIME: 14:31:23; UPDATEUSER: t5459927; SAVECOUNT: 1; INSTANCENAME: INS15645594; REFERENCE TEMPLATE: C; COMPONENTNAME: C_C.Normal_package; NOTE: 1uF 650V
C34 = C_Dup1: ORIGINALSYMBOLORIGIN: (0,4826); COMP: C-CKG57NX7T2J105M500JH; TIME: 14:31:23; UPDATEUSER: t5459927; SAVECOUNT: 1; INSTANCENAME: INS15646846; REFERENCE TEMPLATE: C; COMPONENTNAME: C_C.Normal_package; NOTE: 1uF 650V
C35 = C_Dup1: ORIGINALSYMBOLORIGIN: (0,4826); COMP: C-CKG57NX7T2J105M500JH; TIME: 14:31:23; UPDATEUSER: t5459927; SAVECOUNT: 1; INSTANCENAME: INS15646830; REFERENCE TEMPLATE: C; COMPONENTNAME: C_C.Normal_package; NOTE: 1uF 650V
C36 = C_Dup1: ORIGINALSYMBOLORIGIN: (0,4826); COMP: C-CKG57NX7T2J105M500JH; TIME: 14:31:23; UPDATEUSER: t5459927; SAVECOUNT: 1; INSTANCENAME: INS15646814; REFERENCE TEMPLATE: C; COMPONENTNAME: C_C.Normal_package; NOTE: 1uF 650V
C37 = C_Dup1: ORIGINALSYMBOLORIGIN: (0,4826); COMP: C-CKG57NX7T2J105M500JH; TIME: 14:31:23; UPDATEUSER: t5459927; SAVECOUNT: 1; INSTANCENAME: INS15646798; REFERENCE TEMPLATE: C; COMPONENTNAME: C_C.Normal_package; NOTE: 1uF 650V
C38 = C_Dup1: ORIGINALSYMBOLORIGIN: (0,4826); COMP: C-GRM188R61H105KAALD; TIME: 14:31:23; UPDATEUSER: t5459927; SAVECOUNT: 1; INSTANCENAME: INS16721371; REFERENCE TEMPLATE: C; COMPONENTNAME: C_C.Normal_package; NOTE: 1uF 50V
C39 = C_Dup1: ORIGINALSYMBOLORIGIN: (0,4826); COMP: C-1608_NM; TIME: 14:31:23; UPDATEUSER: t5459927; SAVECOUNT: 1; INSTANCENAME: INS16721315; REFERENCE TEMPLATE: C; COMPONENTNAME: C_C.Normal_package
C40 = C_Dup1: ORIGINALSYMBOLORIGIN: (0,4826); COMP: C-GRM188R61H105KAALD; TIME: 14:31:23; UPDATEUSER: t5459927; SAVECOUNT: 1; INSTANCENAME: INS15595921; REFERENCE TEMPLATE: C; COMPONENTNAME: C_C.Normal_package; NOTE: 1uF 50V
C41 = C_Dup1: ORIGINALSYMBOLORIGIN: (0,4826); COMP: C-GRM31CR61H106MA12L; TIME: 14:31:23; UPDATEUSER: t5459927; SAVECOUNT: 1; INSTANCENAME: INS15595987; REFERENCE TEMPLATE: C; COMPONENTNAME: C_C.Normal_package; NOTE: 10uF 50V
C42 = C_Dup1: ORIGINALSYMBOLORIGIN: (0,4826); COMP: C-GRM31CR61H106MA12L; TIME: 14:31:23; UPDATEUSER: t5459927; SAVECOUNT: 1; INSTANCENAME: INS15596097; REFERENCE TEMPLATE: C; COMPONENTNAME: C_C.Normal_package; NOTE: 10uF 50V
C43 = C_Dup1: ORIGINALSYMBOLORIGIN: (0,4826); COMP: C-GRM188R61H105KAALD; TIME: 14:31:23; UPDATEUSER: t5459927; SAVECOUNT: 1; INSTANCENAME: INS15596075; REFERENCE TEMPLATE: C; COMPONENTNAME: C_C.Normal_package; NOTE: 1uF 50V
C47 = C_Dup1: ORIGINALSYMBOLORIGIN: (0,4826); COMP: C-1608_NM; TIME: 14:31:23; UPDATEUSER: t5459927; SAVECOUNT: 1; INSTANCENAME: INS15596281; REFERENCE TEMPLATE: C; COMPONENTNAME: C_C.Normal_package
C49 = C_Dup1: ORIGINALSYMBOLORIGIN: (0,4826); COMP: C-GRM21BC71E106KE11L; TIME: 14:31:23; UPDATEUSER: t5459927; SAVECOUNT: 1; INSTANCENAME: INS17875665; REFERENCE TEMPLATE: C; COMPONENTNAME: C_C.Normal_package; NOTE: 10uF 25V
D7 = D: UPDATEUSER: t5459927; COMP: D-CMF05; UPDATETIME: 14:31:23; SAVECOUNT: 1; SAVEAREA0: -225,-91,12804,7836; ORIGINALSYMBOLORIGIN: (0,0); FUNCN: D_D.Normal_package; INSTANCENAME: INS15634007
D8 = D: UPDATEUSER: t5459927; COMP: D-CMF05; UPDATETIME: 14:31:23; SAVECOUNT: 1; SAVEAREA0: -225,-91,12804,7836; ORIGINALSYMBOLORIGIN: (0,0); FUNCN: D_D.Normal_package; INSTANCENAME: INS17062002
D9 D10 D15 D16 = SBD: as D3 on sheet 1
D11 = ZD: UPDATEUSER: t5459927; COMP: D-CRY82; UPDATETIME: 14:31:23; SAVECOUNT: 1; SAVEAREA0: -4630,-153,17114,13055; ORIGINALSYMBOLORIGIN: (0,0); FUNCN: ZD_ZD.Normal_package; INSTANCENAME: INS15635127
D12 = ZD: UPDATEUSER: t5459927; COMP: D-KDZVTR2.0B; UPDATETIME: 14:31:23; SAVECOUNT: 1; SAVEAREA0: -4630,-153,17114,13055; ORIGINALSYMBOLORIGIN: (0,0); COMPONENTNAME: ZD_ZD.Normal_package; REFERENCE TEMPLATE: D; INSTANCENAME: INS15595549
D13 = D: UPDATEUSER: t5459927; COMP: D-CMF05; UPDATETIME: 14:31:23; SAVECOUNT: 1; SAVEAREA0: -225,-91,12804,7836; ORIGINALSYMBOLORIGIN: (0,0); INSTANCENAME: INS15634007; COMPONENTNAME: D_D.Normal_package
D14 = D: UPDATEUSER: t5459927; COMP: D-CMF05; UPDATETIME: 14:31:23; SAVECOUNT: 1; SAVEAREA0: -225,-91,12804,7836; ORIGINALSYMBOLORIGIN: (0,0); INSTANCENAME: INS17062002; COMPONENTNAME: D_D.Normal_package
D17 = ZD: UPDATEUSER: t5459927; COMP: D-CRY82; UPDATETIME: 14:31:23; SAVECOUNT: 1; SAVEAREA0: -4630,-153,17114,13055; ORIGINALSYMBOLORIGIN: (0,0); INSTANCENAME: INS15635127; COMPONENTNAME: ZD_ZD.Normal_package
D18 = ZD: UPDATEUSER: t5459927; COMP: D-KDZVTR2.0B; UPDATETIME: 14:31:23; SAVECOUNT: 1; SAVEAREA0: -4630,-153,17114,13055; ORIGINALSYMBOLORIGIN: (0,0); INSTANCENAME: INS15595549; REFERENCE TEMPLATE: D; FUNCN: ZD_ZD.Normal_package
D59 D60 = NC_TO_247: Schottky Barrier Diode; COMP: D-TO-247_NM; MAKER: NC; TIME: 14:31:25; UPDATEUSER: t5459927; SAVECOUNT: 1; OriginalSymbolOrigin: (0,0); INSTANCENAME: INS17322041; COMPONENTNAME: NC_TO-247_NC_TO-247.Normal_package
IC3 IC5 = LP2951D: IC Regurator; COMP: IC-LP2951D; MAKER: Txsas Instruments; TIME: 14:31:24; UPDATEUSER: t5459927; UPDATETIME: 14:27:00; SAVECOUNT: 3; SAVEAREA0: -6711,-14463,34014,2574; OriginalSymbolOrigin: (0,0)
IC4 IC6 = TLP5214A: Gate Driver; COMP: IC-TLP5214A; TIME: 14:31:24; UPDATEUSER: t5459927; UPDATETIME: 14:29:17; SAVECOUNT: 3; SAVEAREA0: -11000,-19257,28193,-2860; OriginalSymbolOrigin: (0,0)
PS2 PS3 = G2412S_2WR2: DCDC Converter; COMP: PS-G2412S-2WR2; MAKER: MORNSUN; NOTE: 24Vin ｱ12Vout; TIME: 14:31:25; UPDATEUSER: t5459927; UPDATETIME: 15:22:21; SAVECOUNT: 2; SAVEAREA0: -5083,-7378,17282,9018; OriginalSymbolOrigin: (0,0)
Q1 = MFNF: SAVEAREA0: -7027,-292,21786,15988; ORIGINALSYMBOLORIGIN: (0,0); COMP: TW060N120C; SAVECOUNT: 1; TIME: 14:31:23; UPDATEUSER: t5459927; FUNCN: MFNF_MFNF.Normal_package; INSTANCENAME: INS15597005
Q2 = MFNF: SAVEAREA0: -7027,-292,21786,15988; ORIGINALSYMBOLORIGIN: (0,0); COMP: TW060N120C; SAVECOUNT: 1; TIME: 14:31:23; UPDATEUSER: t5459927; INSTANCENAME: INS15597005; COMPONENTNAME: MFNF_MFNF.Normal_package
R20 = R: ORIGINALSYMBOLORIGIN: (0,0); COMP: R-RK73H1JTTD7502F; TIME: 14:31:23; UPDATEUSER: t5459927; SAVECOUNT: 1; VAL2: 100mw; NOTE: 75kohm 0.1W; FUNCN: R_R.Normal_package; INSTANCENAME: INS16721339
R21 = R: ORIGINALSYMBOLORIGIN: (0,0); COMP: R-RK73H1JTTD8202F; TIME: 14:31:23; UPDATEUSER: t5459927; SAVECOUNT: 1; VAL2: 100mw; NOTE: 82kohm 0.1W; FUNCN: R_R.Normal_package; INSTANCENAME: INS16721291
R22 = R: ORIGINALSYMBOLORIGIN: (0,0); COMP: R-RK73H1JTTD1002F; TIME: 14:31:23; UPDATEUSER: t5459927; SAVECOUNT: 1; VAL2: 100mw; NOTE: 10kohm 0.1W; FUNCN: R_R.Normal_package; INSTANCENAME: INS16721355
R23 = R: ORIGINALSYMBOLORIGIN: (0,0); COMP: R-RK73B1JTTD471J; TIME: 14:31:23; UPDATEUSER: t5459927; SAVECOUNT: 1; VAL2: 125mw; NOTE: 470ohm 0.1W; FUNCN: R_R.Normal_package; INSTANCENAME: INS15595899
R24 = R: ORIGINALSYMBOLORIGIN: (0,0); COMP: R-ERJ3EKF4700V; TIME: 14:31:23; UPDATEUSER: t5459927; SAVECOUNT: 1; VAL2: 100mw; NOTE: 470ohm 0.1W; FUNCN: R_R.Normal_package; INSTANCENAME: INS17252639
R25 = R: ORIGINALSYMBOLORIGIN: (0,0); COMP: R-1608_NM; TIME: 14:31:23; UPDATEUSER: t5459927; SAVECOUNT: 1; FUNCN: R_R.Normal_package; INSTANCENAME: INS15655219
R26 = R: ORIGINALSYMBOLORIGIN: (0,0); COMP: R-ERJ1TYJ3R3U; TIME: 14:31:23; UPDATEUSER: t5459927; SAVECOUNT: 1; VAL2: 1w; NOTE: 3.3ohm 1W; FUNCN: R_R.Normal_package; INSTANCENAME: INS15655235
R27 = R: PART NUMBER: TMP-430; ORIGINALSYMBOLORIGIN: (0,0); COMP: R-ERJ1TYJ4R7U; TIME: 14:31:23; UPDATEUSER: t5459927; SAVECOUNT: 1; VAL2: 1w; NOTE: 4.7ohm 1W; FUNCN: R_R.Normal_package; INSTANCENAME: INS17252727
R28 = R: ORIGINALSYMBOLORIGIN: (0,0); COMP: R-RK73H1JTTD1001F; TIME: 14:31:23; UPDATEUSER: t5459927; SAVECOUNT: 1; VAL2: 125mw; NOTE: 1.0kohm 0.1W; FUNCN: R_R.Normal_package; INSTANCENAME: INS15596711
R29 = R: ORIGINALSYMBOLORIGIN: (0,0); COMP: R-RK73B1JTTD103J; TIME: 14:31:23; UPDATEUSER: t5459927; SAVECOUNT: 1; VAL2: 100mw; NOTE: 10kohm 0.1W; FUNCN: R_R.Normal_package; INSTANCENAME: INS15595811
R30 = R: ORIGINALSYMBOLORIGIN: (0,0); COMP: R-RK73H1JTTD6801F; TIME: 14:31:23; UPDATEUSER: t5459927; SAVECOUNT: 1; VAL2: 100mw; NOTE: 6.8kohm 0.1W; FUNCN: R_R.Normal_package; INSTANCENAME: INS15596689
R31 = R: ORIGINALSYMBOLORIGIN: (0,0); COMP: R-RK73H1JTTD6801F; TIME: 14:31:23; UPDATEUSER: t5459927; SAVECOUNT: 1; VAL2: 100mw; NOTE: 6.8kohm 0.1W; FUNCN: R_R.Normal_package; INSTANCENAME: INS15596877
R32 = R: ORIGINALSYMBOLORIGIN: (0,0); COMP: R-RK73H1JTTD8202F; TIME: 14:31:23; UPDATEUSER: t5459927; SAVECOUNT: 1; INSTANCENAME: INS16721291; COMPONENTNAME: R_R.Normal_package; NOTE: 82kohm 0.1W; VAL2: 100mw
R33 = R: ORIGINALSYMBOLORIGIN: (0,0); COMP: R-RK73H1JTTD1002F; TIME: 14:31:23; UPDATEUSER: t5459927; SAVECOUNT: 1; INSTANCENAME: INS16721355; COMPONENTNAME: R_R.Normal_package; NOTE: 10kohm 0.1W; VAL2: 100mw
R34 = R: ORIGINALSYMBOLORIGIN: (0,0); COMP: R-RK73H1JTTD7502F; TIME: 14:31:23; UPDATEUSER: t5459927; SAVECOUNT: 1; INSTANCENAME: INS16721339; COMPONENTNAME: R_R.Normal_package; NOTE: 75kohm 0.1W; VAL2: 100mw
R35 = R: ORIGINALSYMBOLORIGIN: (0,0); COMP: R-RK73B1JTTD471J; TIME: 14:31:23; UPDATEUSER: t5459927; SAVECOUNT: 1; INSTANCENAME: INS15595899; COMPONENTNAME: R_R.Normal_package; NOTE: 470ohm 0.1W; VAL2: 125mw
R36 = R: ORIGINALSYMBOLORIGIN: (0,0); COMP: R-ERJ3EKF4700V; TIME: 14:31:23; UPDATEUSER: t5459927; SAVECOUNT: 1; INSTANCENAME: INS17252639; COMPONENTNAME: R_R.Normal_package; NOTE: 470ohm 0.1W; VAL2: 100mw
R37 = R: ORIGINALSYMBOLORIGIN: (0,0); COMP: R-1608_NM; TIME: 14:31:23; UPDATEUSER: t5459927; SAVECOUNT: 1; INSTANCENAME: INS15655219; COMPONENTNAME: R_R.Normal_package
R38 = R: ORIGINALSYMBOLORIGIN: (0,0); COMP: R-ERJ1TYJ3R3U; TIME: 14:31:23; UPDATEUSER: t5459927; SAVECOUNT: 1; INSTANCENAME: INS15655235; COMPONENTNAME: R_R.Normal_package; NOTE: 3.3ohm 1W; VAL2: 1w
R39 = R: PART NUMBER: TMP-430; ORIGINALSYMBOLORIGIN: (0,0); COMP: R-ERJ1TYJ4R7U; TIME: 14:31:23; UPDATEUSER: t5459927; SAVECOUNT: 1; INSTANCENAME: INS17252727; COMPONENTNAME: R_R.Normal_package; NOTE: 4.7ohm 1W; VAL2: 1w
R40 = R: ORIGINALSYMBOLORIGIN: (0,0); COMP: R-RK73H1JTTD1001F; TIME: 14:31:23; UPDATEUSER: t5459927; SAVECOUNT: 1; INSTANCENAME: INS15596711; COMPONENTNAME: R_R.Normal_package; NOTE: 1.0kohm 0.1W; VAL2: 125mw
R41 = R: ORIGINALSYMBOLORIGIN: (0,0); COMP: R-RK73B1JTTD103J; TIME: 14:31:23; UPDATEUSER: t5459927; SAVECOUNT: 1; INSTANCENAME: INS15595811; COMPONENTNAME: R_R.Normal_package; NOTE: 10kohm 0.1W; VAL2: 100mw
R42 = R: ORIGINALSYMBOLORIGIN: (0,0); COMP: R-RK73H1JTTD6801F; TIME: 14:31:23; UPDATEUSER: t5459927; SAVECOUNT: 1; INSTANCENAME: INS15596689; COMPONENTNAME: R_R.Normal_package; NOTE: 6.8kohm 0.1W; VAL2: 100mw
R43 = R: ORIGINALSYMBOLORIGIN: (0,0); COMP: R-RK73H1JTTD6801F; TIME: 14:31:23; UPDATEUSER: t5459927; SAVECOUNT: 1; INSTANCENAME: INS15596877; COMPONENTNAME: R_R.Normal_package; NOTE: 6.8kohm 0.1W; VAL2: 100mw
R173 = R: ORIGINALSYMBOLORIGIN: (0,0); COMP: R-RK73Z2ATTD; TIME: 14:31:23; UPDATEUSER: t5459927; SAVECOUNT: 1; NOTE: 0ohm 0.25w; FUNCN: R_R.Normal_package; INSTANCENAME: INS17875194
R174 = R: ORIGINALSYMBOLORIGIN: (0,0); COMP: R-RK73Z2ATTD; TIME: 14:31:23; UPDATEUSER: t5459927; SAVECOUNT: 1; INSTANCENAME: INS17875194; COMPONENTNAME: R_R.Normal_package; NOTE: 0ohm 0.25w
TB3 = OP_057: Terminal Block; PART NUMBER: TMP-784; COMP: TB-OP-057; MAKER: Osada; NOTE: 85A M5; TIME: 14:31:25; UPDATEUSER: t5459927; SAVECOUNT: 1; SAVEAREA0: -3160,-10780,12927,1014; OriginalSymbolOrigin: (0,0); INSTANCENAME: INS17363781; REFERENCE TEMPLATE: TB; COMPONENTNAME: OP-057_OP-057.Normal_package
TP2-TP11 = TP: TIME: 16:12:21; UPDATEUSER: fukuda-y; UPDATETIME: 16:18:11; SAVECOUNT: 2; SAVEAREA0: -242,-92,12810,7836; OriginalSymbolOrigin: (0,7620); COMP: TP-HK-3-G; VAL3: HK-3-G
U?#2 = WAKU_DEF100: PLOTTIME: HH:MM; SAVEAREA0: 204655,-40163,430411,63902; TIME: 14:30:25; UPDATEUSER: t5459927; UPDATETIME: 14:22:33; SAVECOUNT: 7; OriginalSymbolOrigin: (10160,284480); SHTSAVECOUNT: 17

## Sheet 3.SchDoc
size 420 x 297 mm
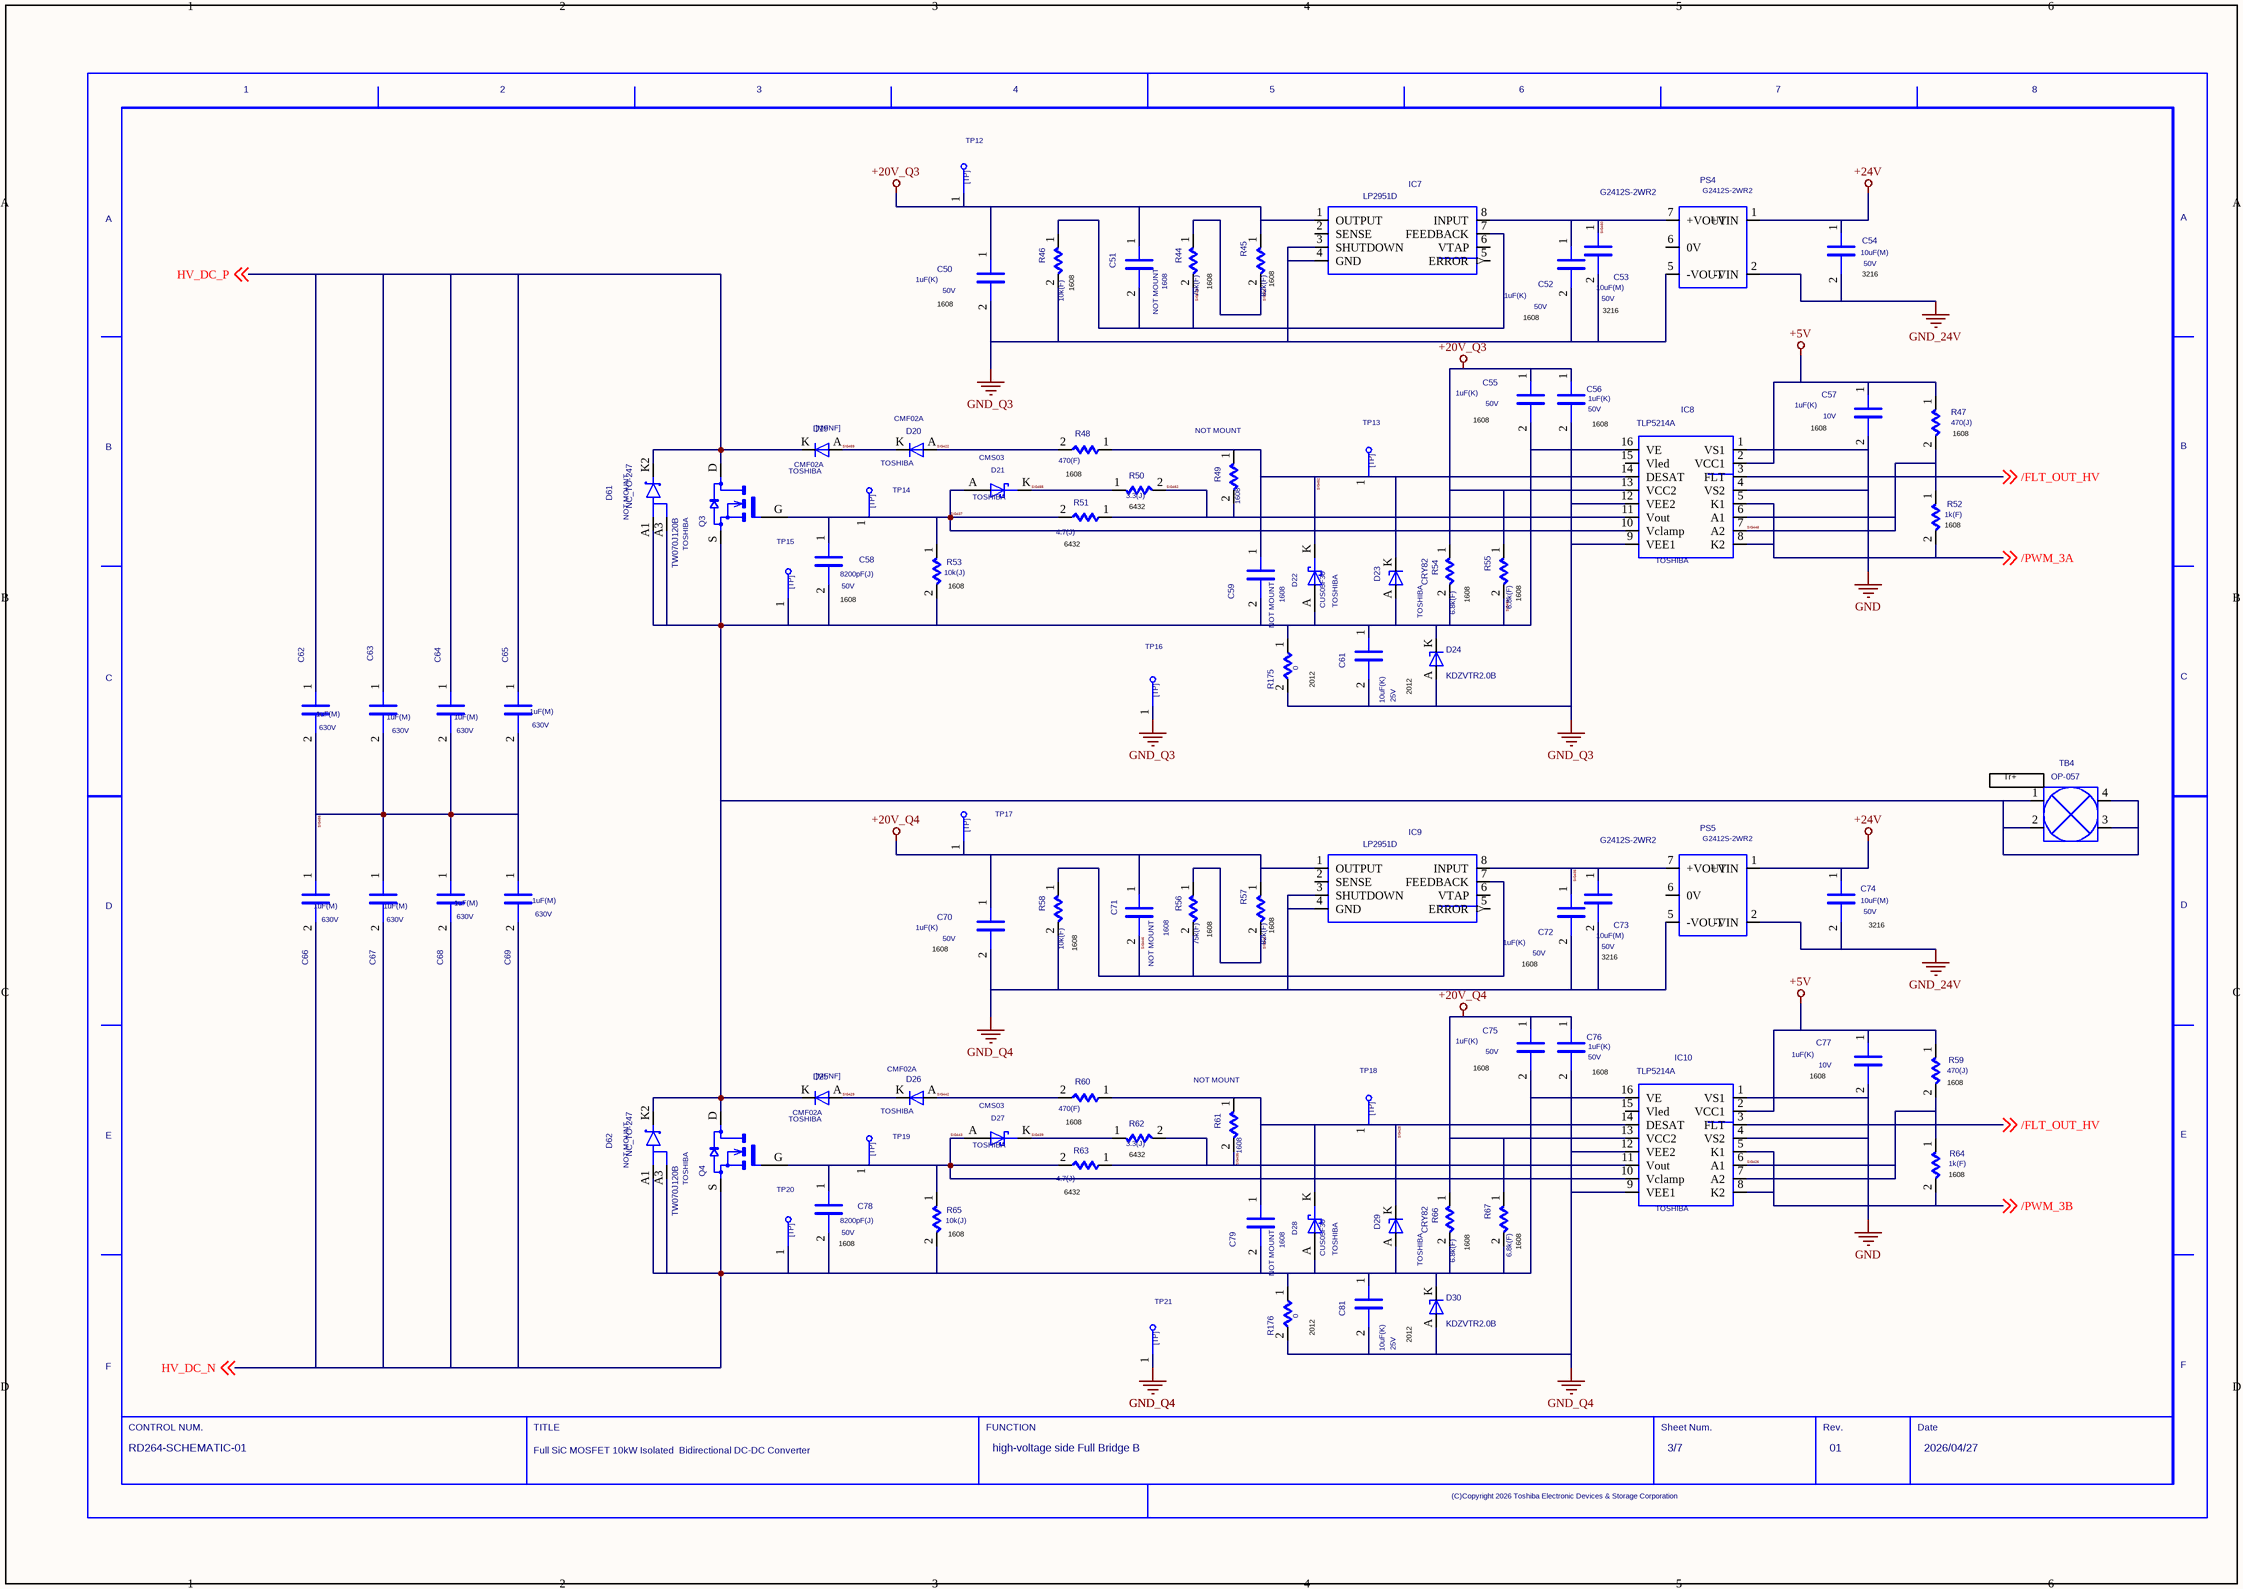
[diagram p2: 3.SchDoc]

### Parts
(Parts that share a designator on the sheet are numbered #1, #2 ... from top to bottom, then left to right.)
C50  VAL2: 50V  VAL1: 1uF(K)  (hidden comment: GRM188R61H105KAALD)
C51  SIZECODESMD: 1608  NOTMOUNT: NOT MOUNT  (hidden comment: NC_C1608)
C52  VAL2: 50V  VAL1: 1uF(K)  (hidden comment: GRM188R61H105KAALD)
C53  VAL2: 50V  VAL1: 10uF(M)  (hidden comment: GRM31CR61H106MA12L)
C54  VAL1: 10uF(M)  VAL2: 50V  (hidden comment: GRM31CR61H106MA12L)
C55  VAL2: 50V  VAL1: 1uF(K)  (hidden comment: GRM188R61H105KAALD)
C56  VAL2: 50V  VAL1: 1uF(K)  (hidden comment: GRM188R61H105KAALD)
C57  VAL2: 10V  VAL1: 1uF(K)  (hidden comment: GRM188R71A105KA61D)
C58  VAL2: 50V  VAL1: 8200pF(J)  (hidden comment: GRM1885C1H332JA01D)
C59  SIZECODESMD: 1608  NOTMOUNT: NOT MOUNT  (hidden comment: NC_C1608)
C61  VAL2: 25V  VAL1: 10uF(K)  (hidden comment: GRM21BC71E106KE11L)
C62  VAL2: 630V  VAL1: 1uF(M)  (hidden comment: CKG57NX7T2J105M500JH)
C63  VAL2: 630V  VAL1: 1uF(M)  (hidden comment: CKG57NX7T2J105M500JH)
C64  VAL2: 630V  VAL1: 1uF(M)  (hidden comment: CKG57NX7T2J105M500JH)
C65  VAL2: 630V  VAL1: 1uF(M)  (hidden comment: CKG57NX7T2J105M500JH)
C66  VAL2: 630V  VAL1: 1uF(M)  (hidden comment: CKG57NX7T2J105M500JH)
C67  VAL2: 630V  VAL1: 1uF(M)  (hidden comment: CKG57NX7T2J105M500JH)
C68  VAL2: 630V  VAL1: 1uF(M)  (hidden comment: CKG57NX7T2J105M500JH)
C69  VAL2: 630V  VAL1: 1uF(M)  (hidden comment: CKG57NX7T2J105M500JH)
C70  VAL2: 50V  VAL1: 1uF(K)  (hidden comment: GRM188R61H105KAALD)
C71  SIZECODESMD: 1608  NOTMOUNT: NOT MOUNT  (hidden comment: NC_C1608)
C72  VAL2: 50V  VAL1: 1uF(K)  (hidden comment: GRM188R61H105KAALD)
C73  VAL2: 50V  VAL1: 10uF(M)  (hidden comment: GRM31CR61H106MA12L)
C74  VAL2: 50V  VAL1: 10uF(M)  (hidden comment: GRM31CR61H106MA12L)
C75  VAL1: 1uF(K)  VAL2: 50V  (hidden comment: GRM188R61H105KAALD)
C76  VAL2: 50V  VAL1: 1uF(K)  (hidden comment: GRM188R61H105KAALD)
C77  VAL1: 1uF(K)  VAL2: 10V  (hidden comment: GRM188R71A105KA61D)
C78  VAL2: 50V  VAL1: 8200pF(J)  (hidden comment: GRM1885C1H332JA01D)
C79  SIZECODESMD: 1608  NOTMOUNT: NOT MOUNT  (hidden comment: NC_C1608)
C81  VAL2: 25V  VAL1: 10uF(K)  (hidden comment: GRM21BC71E106KE11L)
D19  USERCOMPTEXT3: TOSHIBA  VAL3: CMF02A  (hidden comment: CMF05)
D20  USERCOMPTEXT3: TOSHIBA  VAL3: CMF02A  (hidden comment: CMF05)
D21  VAL3: CMS03  USERCOMPTEXT3: TOSHIBA  (hidden comment: SBD)
D22  VAL3: CUS05F30  USERCOMPTEXT3: TOSHIBA  (hidden comment: SBD)
D23  CRY82  USERCOMPTEXT3: TOSHIBA
D24  KDZVTR2.0B
D25  USERCOMPTEXT3: TOSHIBA  VAL3: CMF02A  (hidden comment: CMF05)
D26  USERCOMPTEXT3: TOSHIBA  VAL3: CMF02A  (hidden comment: CMF05)
D27  VAL3: CMS03  USERCOMPTEXT3: TOSHIBA  (hidden comment: SBD)
D28  VAL3: CUS05F30  USERCOMPTEXT3: TOSHIBA  (hidden comment: SBD)
D29  CRY82  USERCOMPTEXT3: TOSHIBA
D30  KDZVTR2.0B
D61  NC_TO-247  NOTMOUNT: NOT MOUNT
D62  NC_TO-247  NOTMOUNT: NOT MOUNT
IC7  LP2951D
IC8  TLP5214A  USERCOMPTEXT3: TOSHIBA
IC9  LP2951D
IC10  TLP5214A  USERCOMPTEXT3: TOSHIBA
PS4  G2412S-2WR2
PS5  G2412S-2WR2
Q3  TW070J120B  USERCOMPTEXT3: TOSHIBA
Q4  TW070J120B  USERCOMPTEXT3: TOSHIBA
R44  VAL1: 75k(F)  (hidden comment: RK73H1JTTD7502F)
R45  VAL1: 82k(F)  (hidden comment: RK73H1JTTD8202F)
R46  VAL1: 10k(F)  (hidden comment: RK73H1JTTD1002F)
R47  VAL1: 470(J)  (hidden comment: RK73B1JTTD471J)
R48  VAL1: 470(F)  (hidden comment: ERJ3EKF4700V)
R49  SIZECODESMD: 1608  NOTMOUNT: NOT MOUNT  (hidden comment: NC_R1608)
R50  VAL1: 3.3(J)  (hidden comment: ERJ1TYJ3R3U)
R51  VAL1: 4.7(J)  (hidden comment: ERJ1TYJ4R7U)
R52  VAL1: 1k(F)  (hidden comment: RK73H1JTTD1001F)
R53  VAL1: 10k(J)  (hidden comment: RK73B1JTTD103J)
R54  VAL1: 6.8k(F)  (hidden comment: RK73H1JTTD6801F)
R55  VAL1: 6.8k(F)  (hidden comment: RK73H1JTTD6801F)
R56  VAL1: 75k(F)  (hidden comment: RK73H1JTTD7502F)
R57  VAL1: 82k(F)  (hidden comment: RK73H1JTTD8202F)
R58  VAL1: 10k(F)  (hidden comment: RK73H1JTTD1002F)
R59  VAL1: 470(J)  (hidden comment: RK73B1JTTD471J)
R60  VAL1: 470(F)  (hidden comment: ERJ3EKF4700V)
R61  SIZECODESMD: 1608  NOTMOUNT: NOT MOUNT  (hidden comment: NC_R1608)
R62  VAL1: 3.3(J)  (hidden comment: ERJ1TYJ3R3U)
R63  VAL1: 4.7(J)  (hidden comment: ERJ1TYJ4R7U)
R64  VAL1: 1k(F)  (hidden comment: RK73H1JTTD1001F)
R65  VAL1: 10k(J)  (hidden comment: RK73B1JTTD103J)
R66  VAL1: 6.8k(F)  (hidden comment: RK73H1JTTD6801F)
R67  VAL1: 6.8k(F)  (hidden comment: RK73H1JTTD6801F)
R175  VAL1: 0  (hidden comment: RK73Z2ATTD)
R176  VAL1: 0  (hidden comment: RK73Z2ATTD)
TB4  OP-057
TP12  TP  (value not drawn)
TP13  TP  (value not drawn)
TP14  TP  (value not drawn)
TP15  TP  (value not drawn)
TP16  TP  (value not drawn)
TP17  TP  (value not drawn)
TP18  TP  (value not drawn)
TP19  TP  (value not drawn)
TP20  TP  (value not drawn)
TP21  TP  (value not drawn)
U?#3  DATE: 2026/04/27  DRAWINGNUMBER: RD264-SCHEMATIC-01  TITLE: Full SiC MOSFET 10kW Isolated / Bidirectional DC-DC Converter  FUNCTION: high-voltage side Full Bridge B  SHEETNUMBER: 3/7  REVISION: 01  (hidden comment: WAKU_DEF100)

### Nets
+5V: C57.1 C77.1 IC8.2(VCC1) IC10.2(VCC1) R47.1 R59.1
+20V_Q3: C50.1 C51.1 C55.1 C56.1 IC7.1(OUTPUT) IC8.13(VCC2) R45.1 R54.1 R55.1 TP12.1
+20V_Q4: C70.1 C71.1 C75.1 C76.1 IC9.1(OUTPUT) IC10.13(VCC2) R57.1 R66.1 R67.1 TP17.1
+24V: C54.1 C74.1 PS4.1(+VIN) PS5.1(+VIN)
GND: C57.2 C77.2 IC8.1(VS1) IC8.4(VS2) IC10.1(VS1) IC10.4(VS2)
GND_24V: C54.2 C74.2 PS4.2(-VIN) PS5.2(-VIN)
GND_Q3: C50.2 C52.2 C53.2 C56.2 C61.2 D24.A IC7.3(SHUTDOWN) IC7.4(GND) IC8.9(VEE1) IC8.12(VEE2) PS4.5(-VOUT) R46.2 R175.2 TP16.1
GND_Q4: C70.2 C72.2 C73.2 C76.2 C81.2 D30.A IC9.3(SHUTDOWN) IC9.4(GND) IC10.9(VEE1) IC10.12(VEE2) PS5.5(-VOUT) R58.2 R176.2 TP21.1
/FLT_OUT_HV: IC8.3(FLT) IC10.3(FLT) ; off-sheet /FLT_OUT_HV
/PWM_3A: IC8.5(K1) IC8.8(K2) R52.2 ; off-sheet /PWM_3A
/PWM_3B: IC10.5(K1) IC10.8(K2) R64.2 ; off-sheet /PWM_3B
HV_DC_N: C66.2 C67.2 C68.2 C69.2 C75.2 C78.2 C79.2 C81.1 D28.A D29.A D30.K(C) D62.A1 D62.A3 IC10.16(VE) Q4.S R65.2 R66.2 R67.2 R176.1 TP20.1 ; off-sheet HV_DC_N
HV_DC_P: C62.1 C63.1 C64.1 C65.1 D19.K(C) D61.K2 Q3.D ; off-sheet HV_DC_P
SIG418: C51.2 IC7.7(FEEDBACK) R44.2 R46.1
SIG422: D20.A R48.2
SIG424: R44.1 R45.2
SIG426: IC10.6(A1) IC10.7(A2) R59.2 R64.1
SIG428: C79.1 D28.K(C) D29.K(C) IC10.14(DESAT) R60.1 R61.1 TP18.1
SIG429: D25.A D26.K(C)
SIG435: C72.1 C73.1 IC9.8(INPUT) PS5.7(+VOUT)
SIG436: IC10.11(Vout) R61.2 R62.2 R63.1
SIG437: C58.1 D21.A IC8.10(Vclamp) Q3.G R51.2 R53.1 TP14.1
SIG439: D27.K(C) R62.1
SIG442: D26.A R60.2
SIG443: C78.1 D27.A IC10.10(Vclamp) Q4.G R63.2 R65.1 TP19.1
SIG444: R56.1 R57.2
SIG446: C71.2 IC9.7(FEEDBACK) R56.2 R58.1
SIG448: IC8.6(A1) IC8.7(A2) R47.2 R52.1
SIG452: C59.1 D22.K(C) D23.K(C) IC8.14(DESAT) R48.1 R49.1 TP13.1
SIG454: C55.2 C58.2 C59.2 C61.1 D22.A D23.A D24.K(C) D25.K(C) D61.A1 D61.A3 D62.K2 IC8.16(VE) Q3.S Q4.D R53.2 R54.2 R55.2 R175.1 TB4.1 TB4.2 TB4.3 TB4.4 TP15.1
SIG455: D21.K(C) R50.1
SIG456: C62.2 C63.2 C64.2 C65.2 C66.1 C67.1 C68.1 C69.1
SIG459: D19.A D20.K(C)
SIG460: C52.1 C53.1 IC7.8(INPUT) PS4.7(+VOUT)
SIG462: IC8.11(Vout) R49.2 R50.2 R51.1

Not connected (* = marked no-connect by the designer): IC7 2(SENSE) 5(ERROR) 6(VTAP); IC8 15(Vled); IC9 2(SENSE) 5(ERROR) 6(VTAP); IC10 15(Vled); PS4 6(0V); PS5 6(0V)

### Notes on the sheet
- (near C50) 1608
- (near R46) 1608
- (near R44) 1608
- (near R45) 1608
- 1608
- 3216
- (near C54) 3216
- (near C55) 1608
- (near C56) 1608
- (near C57) 1608
- (near R47) 1608
- (near R48) 1608
- (near R50) 6432
- (near R52) 1608
- (near R53) 1608
- (near R51) 6432
- (near R54) 1608
- (near R55) 1608
- (near C58) 1608
- (near R175) 2012
- 2012
- (near TB4) Tr+
- (near R56) 1608
- (near R57) 1608
- (near C74) 3216
- (near C70) 1608
- (near R58) 1608
- (near C75) 1608
- (near C76) 1608
- (near R60) 1608
- (near C77) 1608
- (near R59) 1608
- (near R63) 6432
- (near R62) 6432
- (near R64) 1608
- (near C78) 1608
- (near R65) 1608
- (near R66) 1608
- (near R67) 1608
- (near R176) 2012

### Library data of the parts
C50 C70 = C_Dup1: as C18 on sheet 2
C51 C71 = C_Dup1: as C19 on sheet 2
C52 C72 = C_Dup1: as C20 on sheet 2
C53 C73 = C_Dup1: as C21 on sheet 2
C54 = C_Dup1: as C42 on sheet 2
C55 = C_Dup1: as C23 on sheet 2
C56 C76 = C_Dup1: ORIGINALSYMBOLORIGIN: (0,4826); COMP: C-GRM188R61H105KAALD; TIME: 14:31:23; UPDATEUSER: t5459927; SAVECOUNT: 1; NOTE: 1uF 50V; FUNCN: C_C.Normal_package; REFERENCE TEMPLATE: C; INSTANCENAME: INS15596185
C57 = C_Dup1: ORIGINALSYMBOLORIGIN: (0,4826); COMP: C-GRM188R71A105KA61D; TIME: 14:31:23; UPDATEUSER: t5459927; SAVECOUNT: 1; NOTE: 1uF 10V; FUNCN: C_C.Normal_package; REFERENCE TEMPLATE: C; INSTANCENAME: INS15595789
C58 C78 = C_Dup1: ORIGINALSYMBOLORIGIN: (0,4826); COMP: C-GRM1885C1H332JA01D; TIME: 14:31:23; UPDATEUSER: t5459927; SAVECOUNT: 1; NOTE: 3300pF 50V; FUNCN: C_C.Normal_package; REFERENCE TEMPLATE: C; INSTANCENAME: INS15595745
C59 C79 = C_Dup1: as C27 on sheet 2
C61 C81 = C_Dup1: as C31 on sheet 2
C62 = C_Dup1: ORIGINALSYMBOLORIGIN: (0,4826); COMP: C-CKG57NX7T2J105M500JH; TIME: 14:31:23; UPDATEUSER: t5459927; SAVECOUNT: 1; NOTE: 1uF 650V; FUNCN: C_C.Normal_package; REFERENCE TEMPLATE: C; INSTANCENAME: INS15645741
C63 = C_Dup1: ORIGINALSYMBOLORIGIN: (0,4826); COMP: C-CKG57NX7T2J105M500JH; TIME: 14:31:23; UPDATEUSER: t5459927; SAVECOUNT: 1; NOTE: 1uF 650V; FUNCN: C_C.Normal_package; REFERENCE TEMPLATE: C; INSTANCENAME: INS15645594
C64 = C_Dup1: ORIGINALSYMBOLORIGIN: (0,4826); COMP: C-CKG57NX7T2J105M500JH; TIME: 14:31:23; UPDATEUSER: t5459927; SAVECOUNT: 1; NOTE: 1uF 650V; FUNCN: C_C.Normal_package; REFERENCE TEMPLATE: C; INSTANCENAME: INS15645445
C65 = C_Dup1: ORIGINALSYMBOLORIGIN: (0,4826); COMP: C-CKG57NX7T2J105M500JH; TIME: 14:31:23; UPDATEUSER: t5459927; SAVECOUNT: 1; NOTE: 1uF 650V; FUNCN: C_C.Normal_package; REFERENCE TEMPLATE: C; INSTANCENAME: INS15645292
C66 = C_Dup1: ORIGINALSYMBOLORIGIN: (0,4826); COMP: C-CKG57NX7T2J105M500JH; TIME: 14:31:23; UPDATEUSER: t5459927; SAVECOUNT: 1; NOTE: 1uF 650V; FUNCN: C_C.Normal_package; REFERENCE TEMPLATE: C; INSTANCENAME: INS15646846
C67 = C_Dup1: ORIGINALSYMBOLORIGIN: (0,4826); COMP: C-CKG57NX7T2J105M500JH; TIME: 14:31:23; UPDATEUSER: t5459927; SAVECOUNT: 1; NOTE: 1uF 650V; FUNCN: C_C.Normal_package; REFERENCE TEMPLATE: C; INSTANCENAME: INS15646830
C68 = C_Dup1: ORIGINALSYMBOLORIGIN: (0,4826); COMP: C-CKG57NX7T2J105M500JH; TIME: 14:31:23; UPDATEUSER: t5459927; SAVECOUNT: 1; NOTE: 1uF 650V; FUNCN: C_C.Normal_package; REFERENCE TEMPLATE: C; INSTANCENAME: INS15646814
C69 = C_Dup1: ORIGINALSYMBOLORIGIN: (0,4826); COMP: C-CKG57NX7T2J105M500JH; TIME: 14:31:23; UPDATEUSER: t5459927; SAVECOUNT: 1; NOTE: 1uF 650V; FUNCN: C_C.Normal_package; REFERENCE TEMPLATE: C; INSTANCENAME: INS15646798
C74 = C_Dup1: as C22 on sheet 2
C75 = C_Dup1: as C43 on sheet 2
C77 = C_Dup1: as C25 on sheet 2
D19 D25 = D: as D7 on sheet 2
D20 D26 = D: as D8 on sheet 2
D21 D22 D27 D28 = SBD: as D3 on sheet 1
D23 D29 = ZD: as D11 on sheet 2
D24 D30 = ZD: as D12 on sheet 2
D61 D62 = NC_TO_247: as D59 on sheet 2
IC7 IC9 = LP2951D: as IC3 on sheet 2
IC8 IC10 = TLP5214A: as IC4 on sheet 2
PS4 PS5 = G2412S_2WR2: as PS2 on sheet 2
Q3 = MFNF: as Q2 on sheet 2
Q4 = MFNF: as Q1 on sheet 2
R44 R56 = R: as R20 on sheet 2
R45 R57 = R: as R21 on sheet 2
R46 R58 = R: as R22 on sheet 2
R47 R59 = R: as R23 on sheet 2
R48 R60 = R: as R24 on sheet 2
R49 R61 = R: as R25 on sheet 2
R50 R62 = R: as R26 on sheet 2
R51 R63 = R: as R27 on sheet 2
R52 R64 = R: as R28 on sheet 2
R53 R65 = R: as R29 on sheet 2
R54 R66 = R: as R30 on sheet 2
R55 R67 = R: as R31 on sheet 2
R175 = R: as R174 on sheet 2
R176 = R: as R173 on sheet 2
TB4 = OP_057: as TB3 on sheet 2
TP12-TP21 = TP: as TP2 on sheet 2
U?#3 = WAKU_DEF100: as U?#1 on sheet 1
